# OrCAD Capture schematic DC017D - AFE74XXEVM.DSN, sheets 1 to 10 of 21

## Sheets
1 SHEET 21 - HARDWARE: size B; title: HARDWARE; rev: D; note: DC017 - AFE74XXEVM
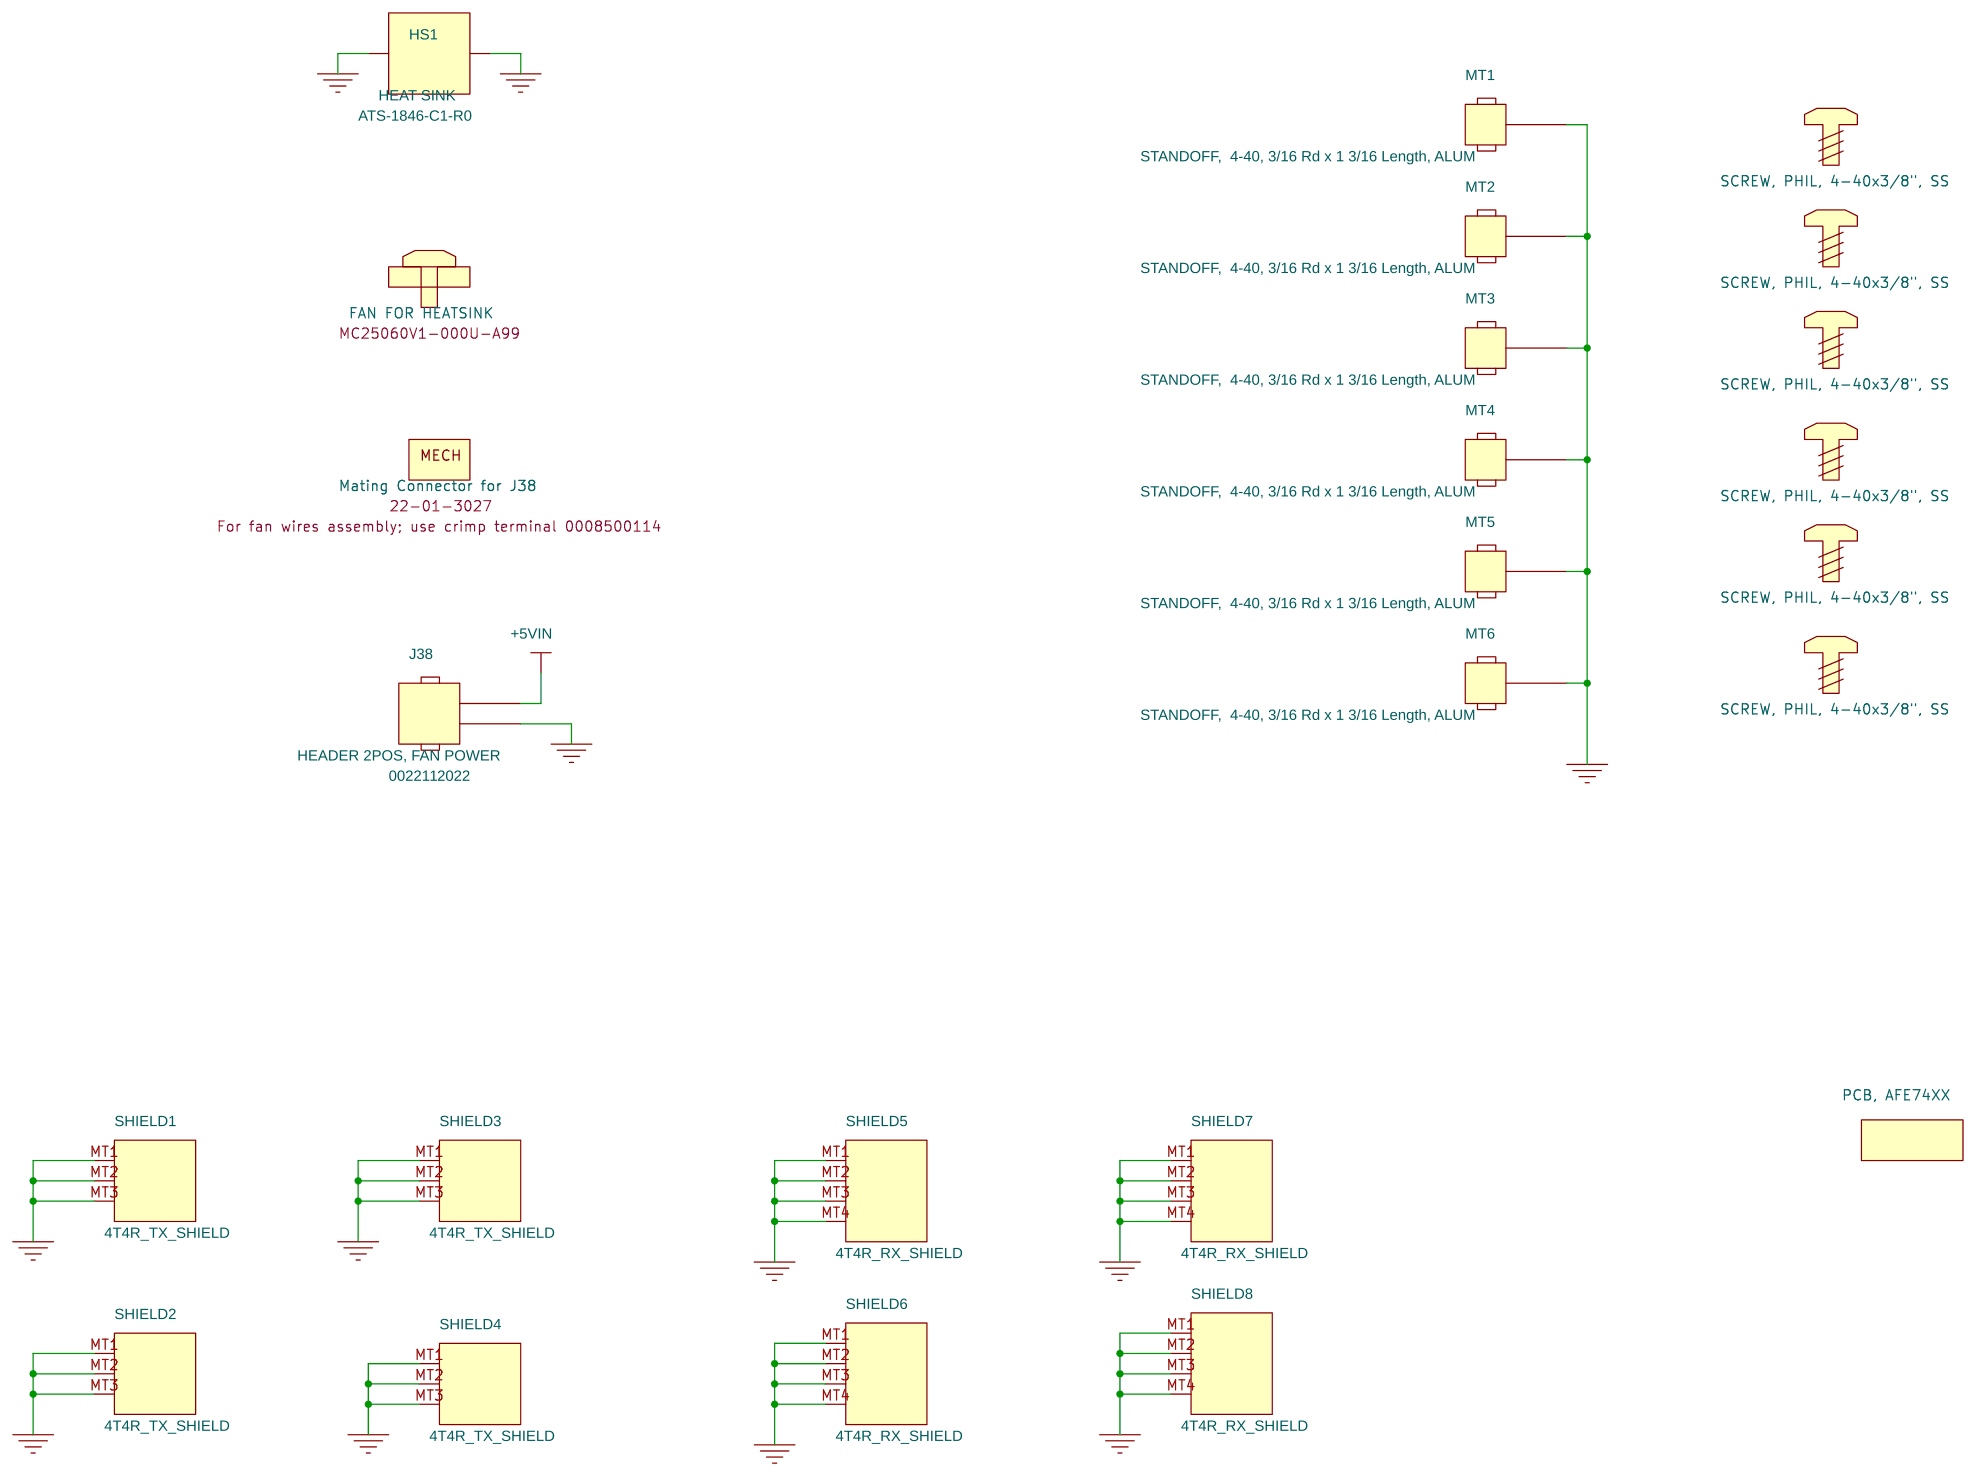
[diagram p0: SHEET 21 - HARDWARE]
2 SHEET 20 - POWER SUPPLIES: size B; title: POWER SUPPLIES +.9V, +1.8V
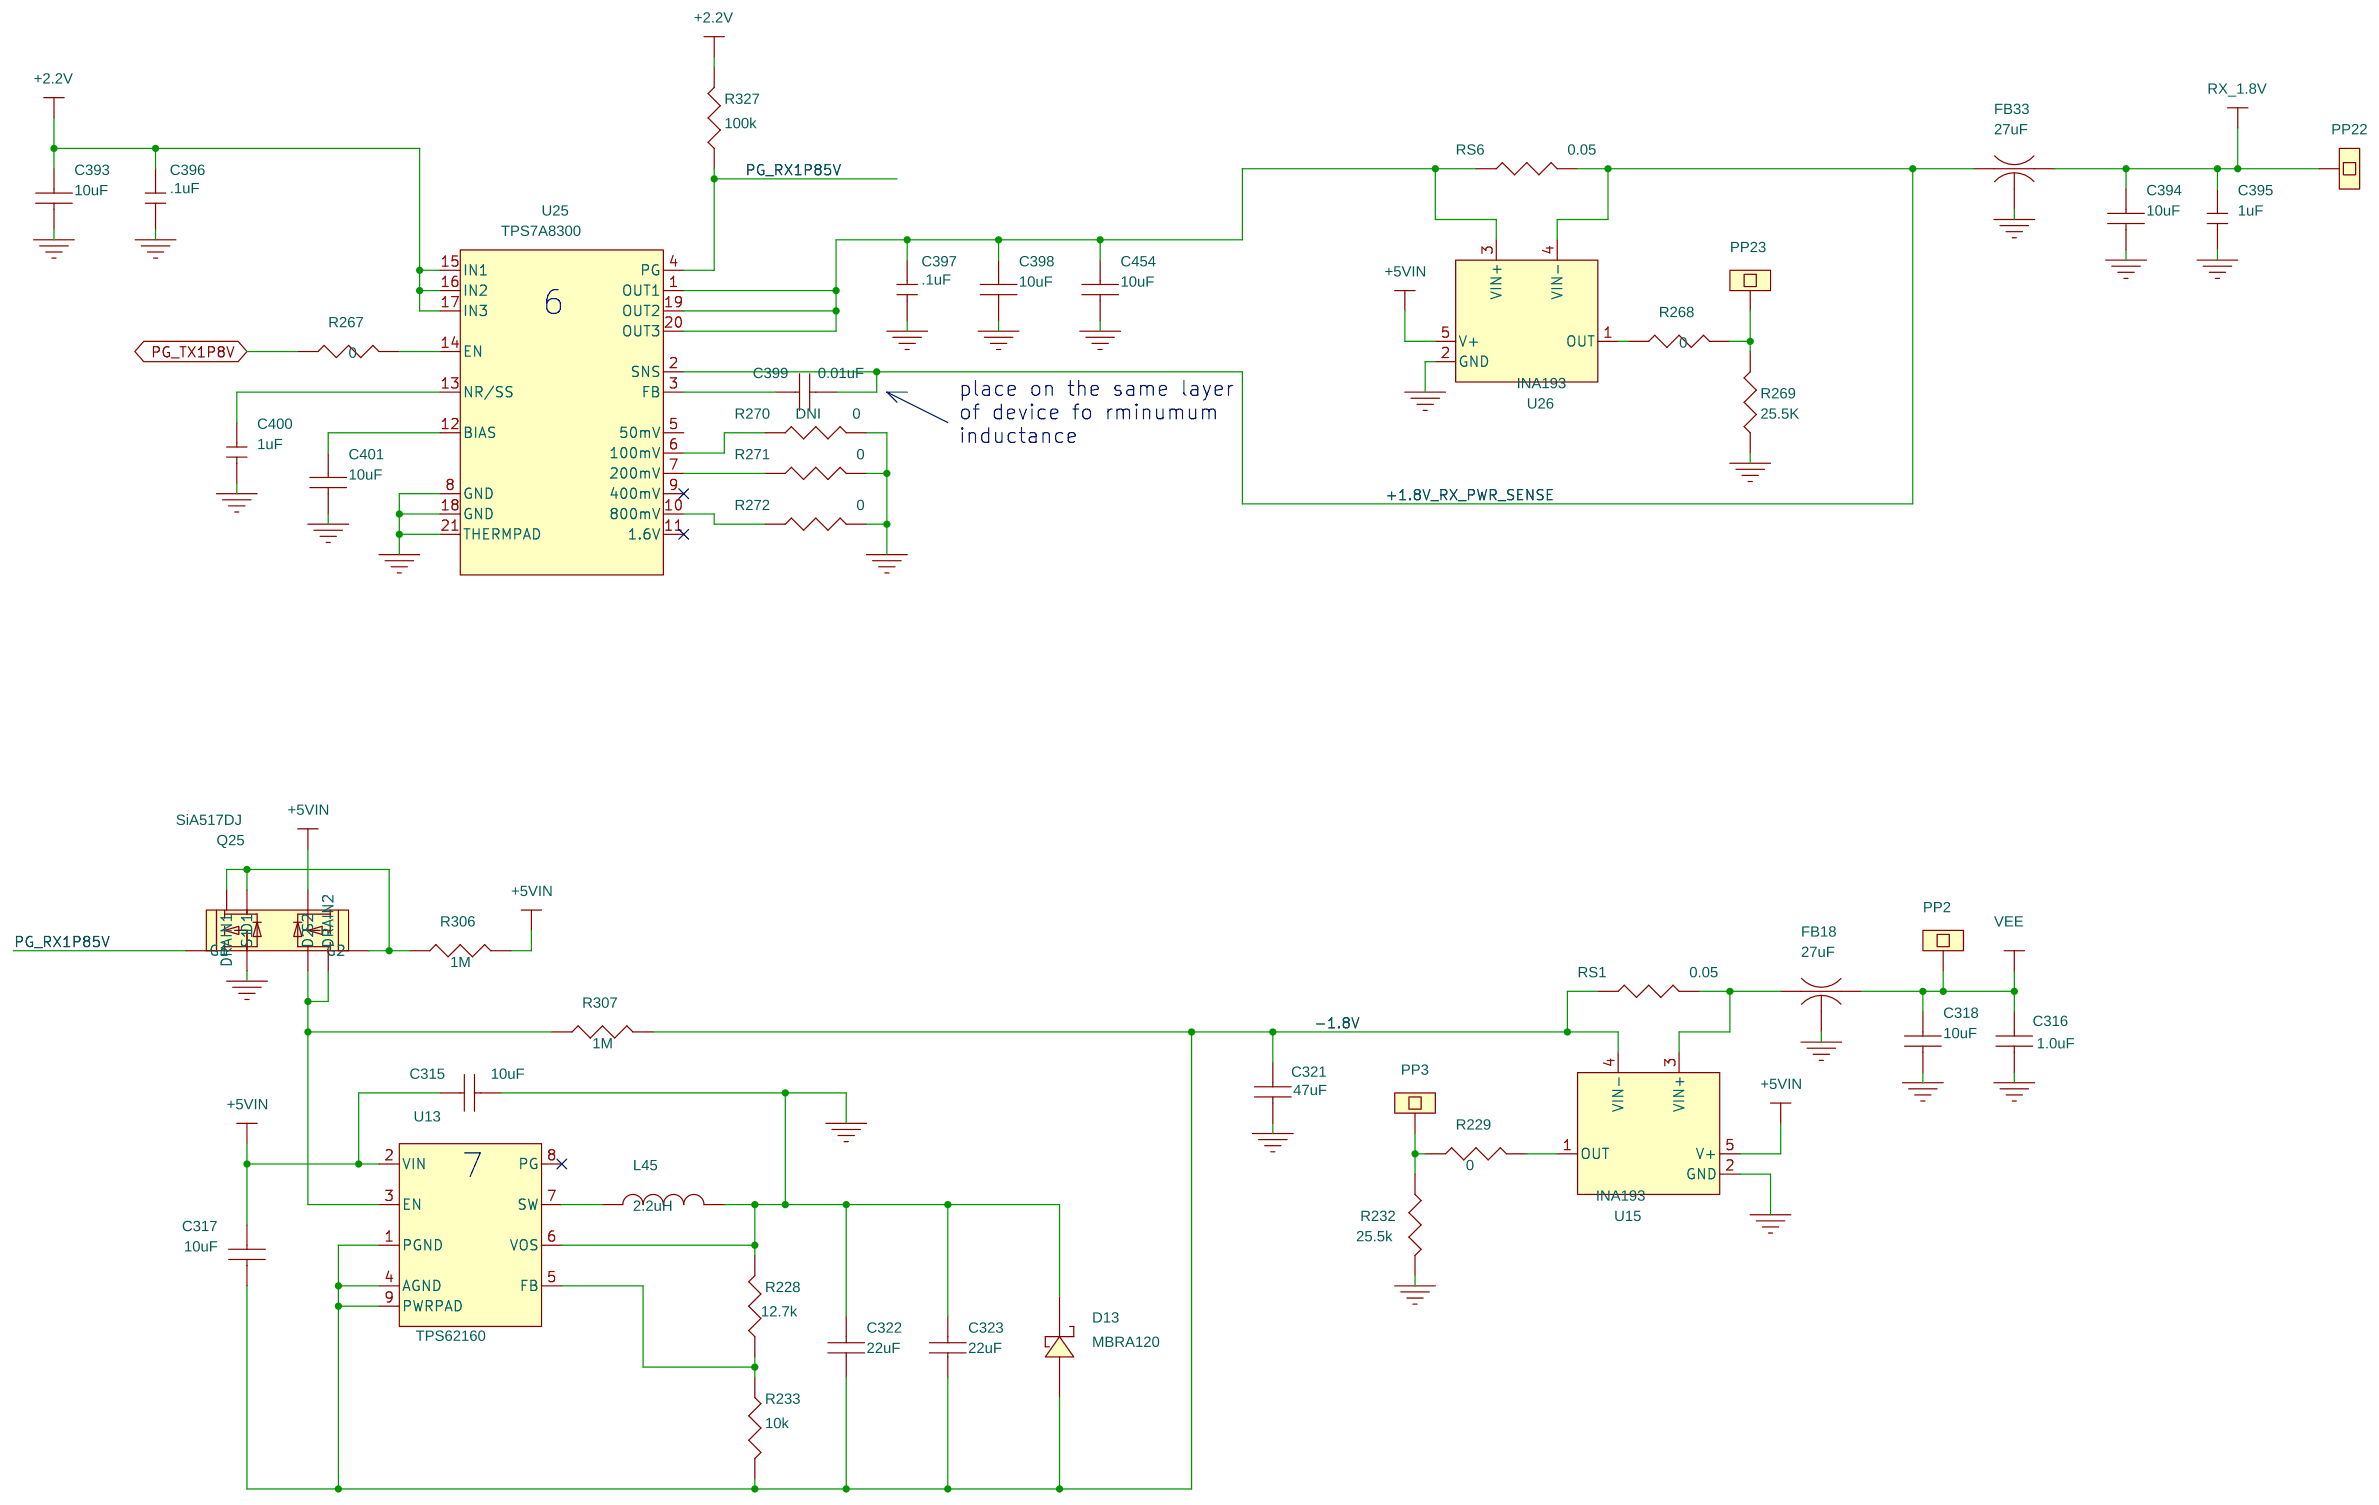
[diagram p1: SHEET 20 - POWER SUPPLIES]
3 SHEET 01 - COVER: title: COVER
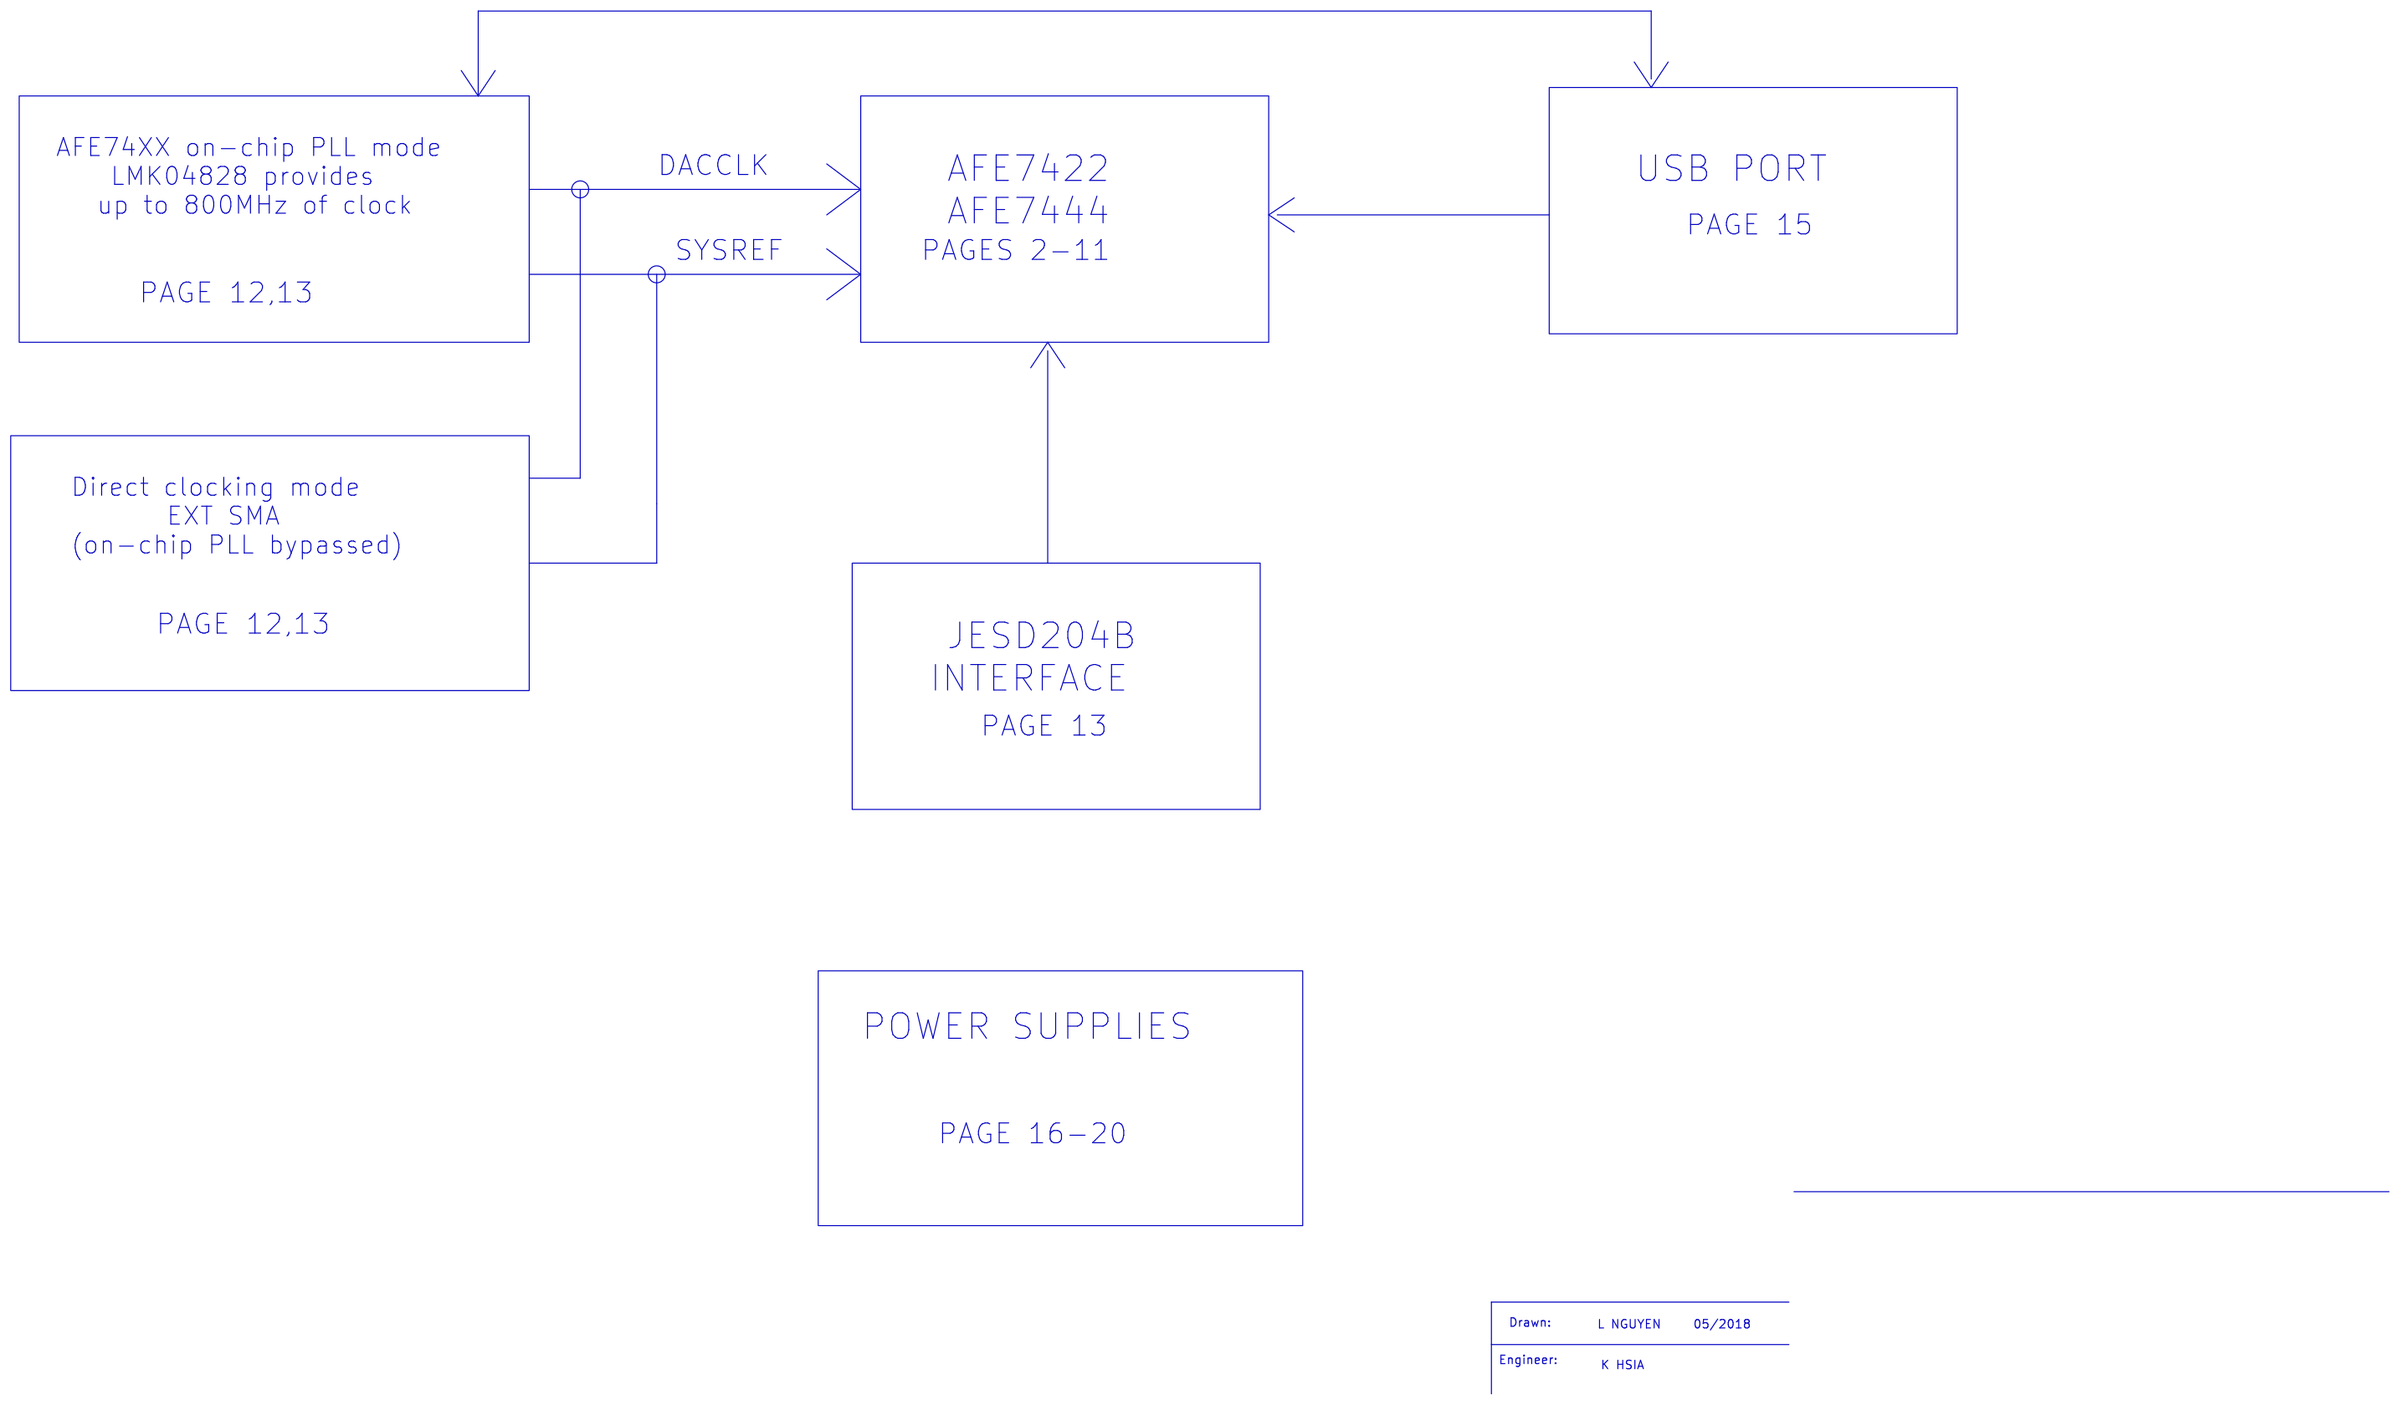
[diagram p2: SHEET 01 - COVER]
4 SHEET 02 - AFE RX & TX: size B; title: AFE CLKp/m, CLKOUTp/m, SYSREFp/m
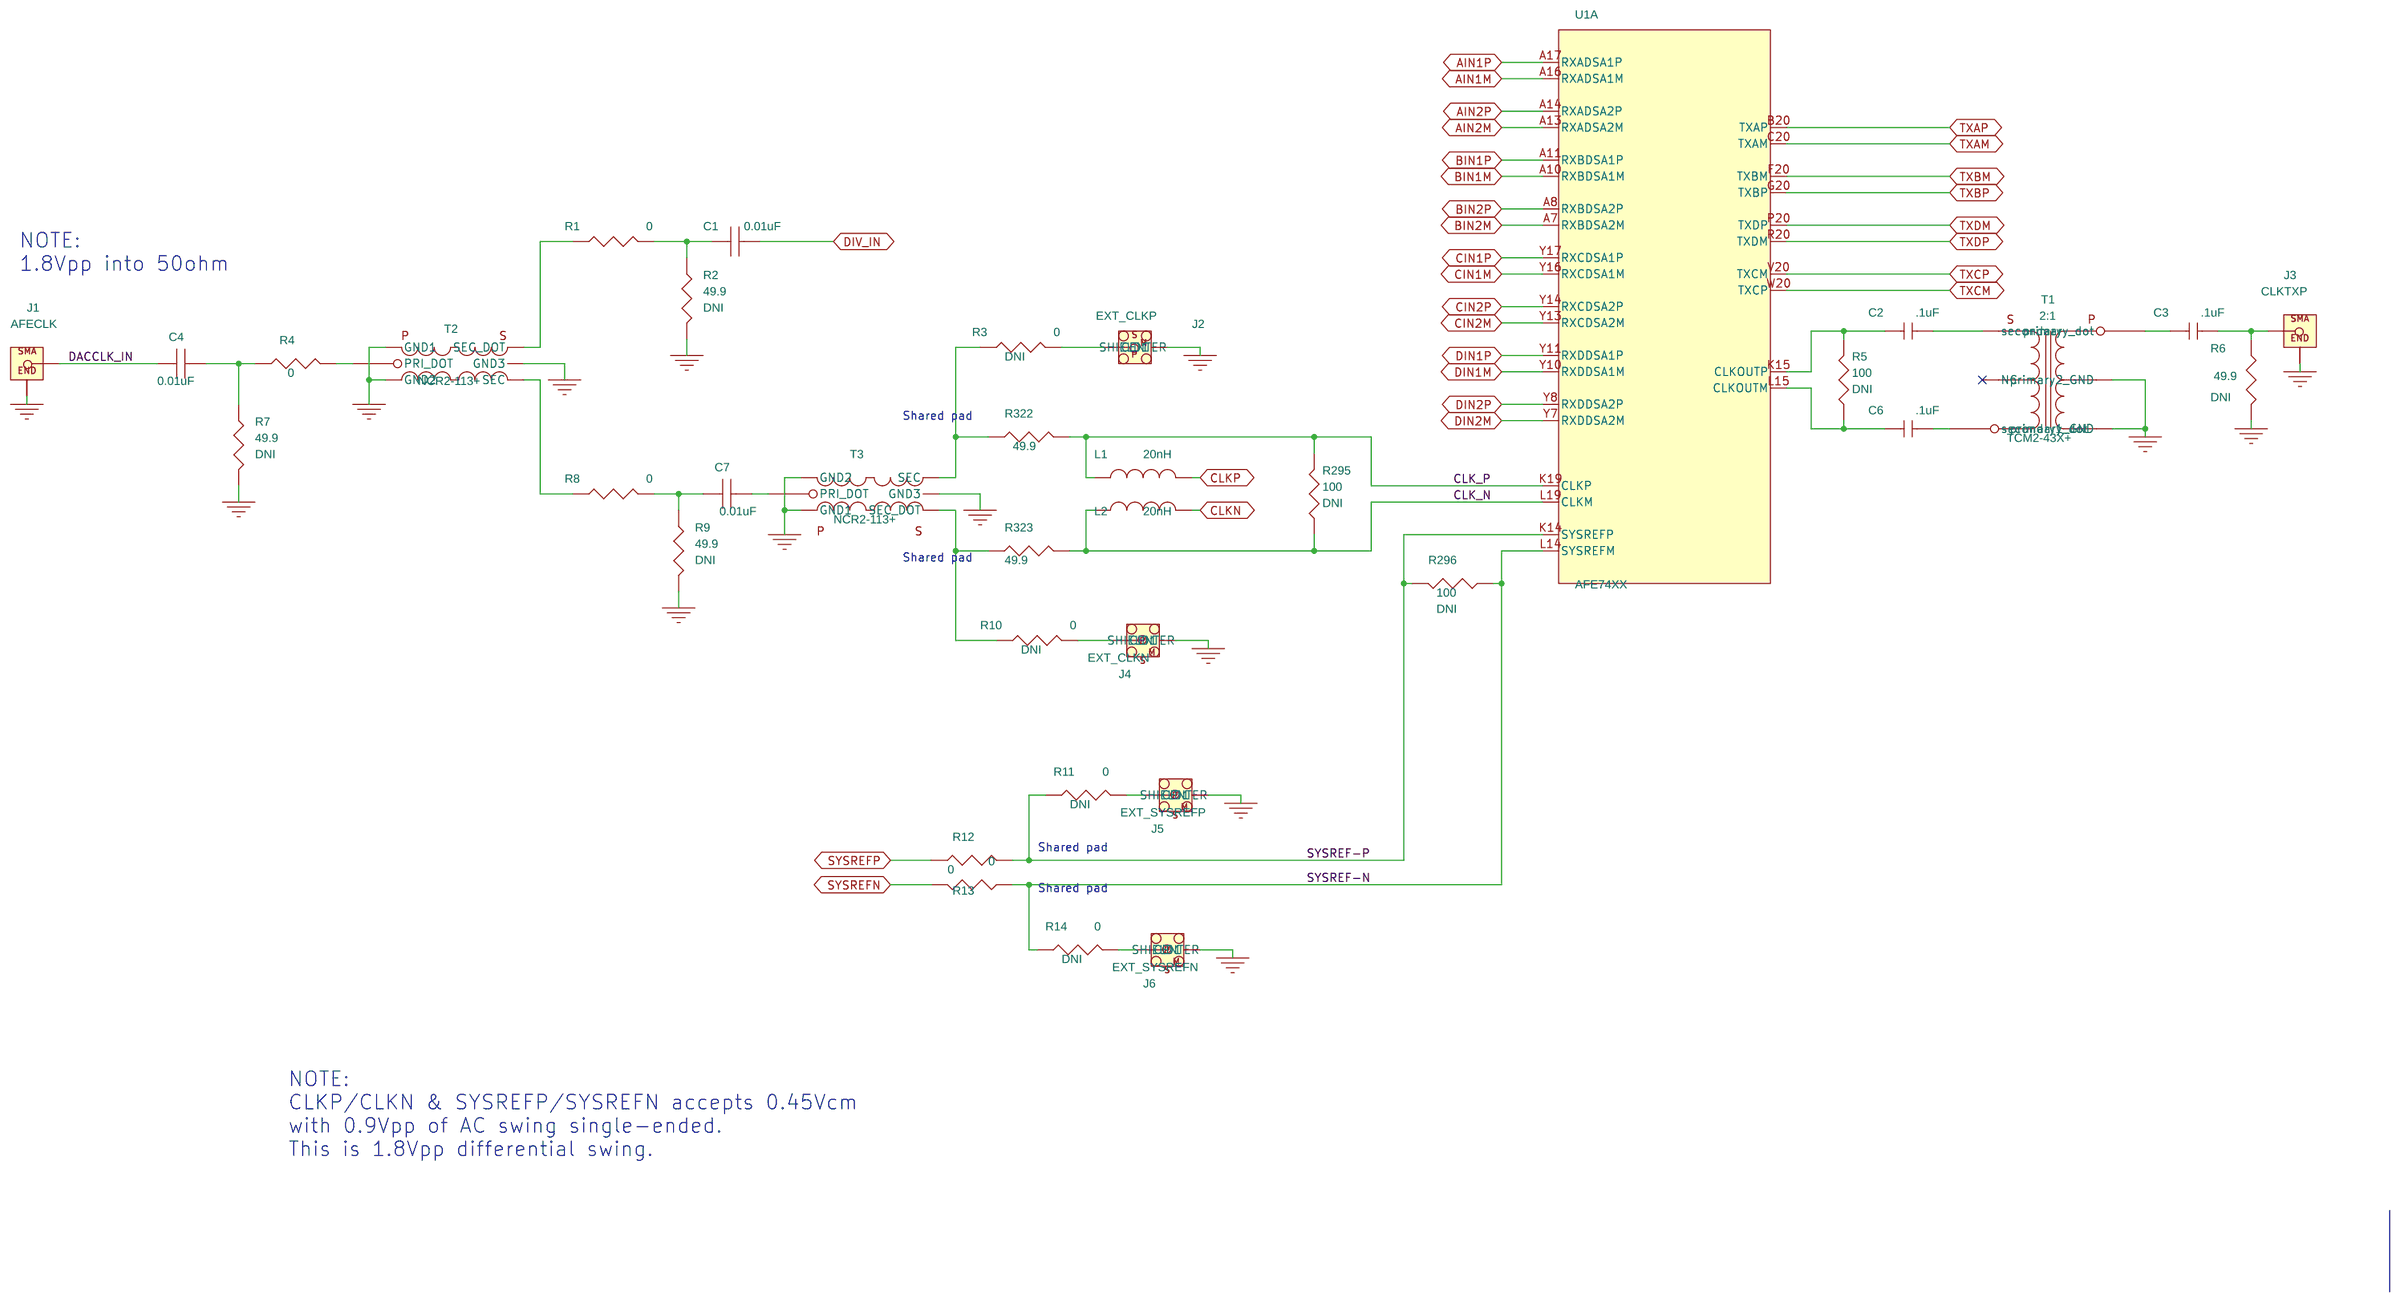
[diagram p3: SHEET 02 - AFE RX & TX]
5 SHEET 03 - AFE Serdes: size B; title: Serdes Lanes
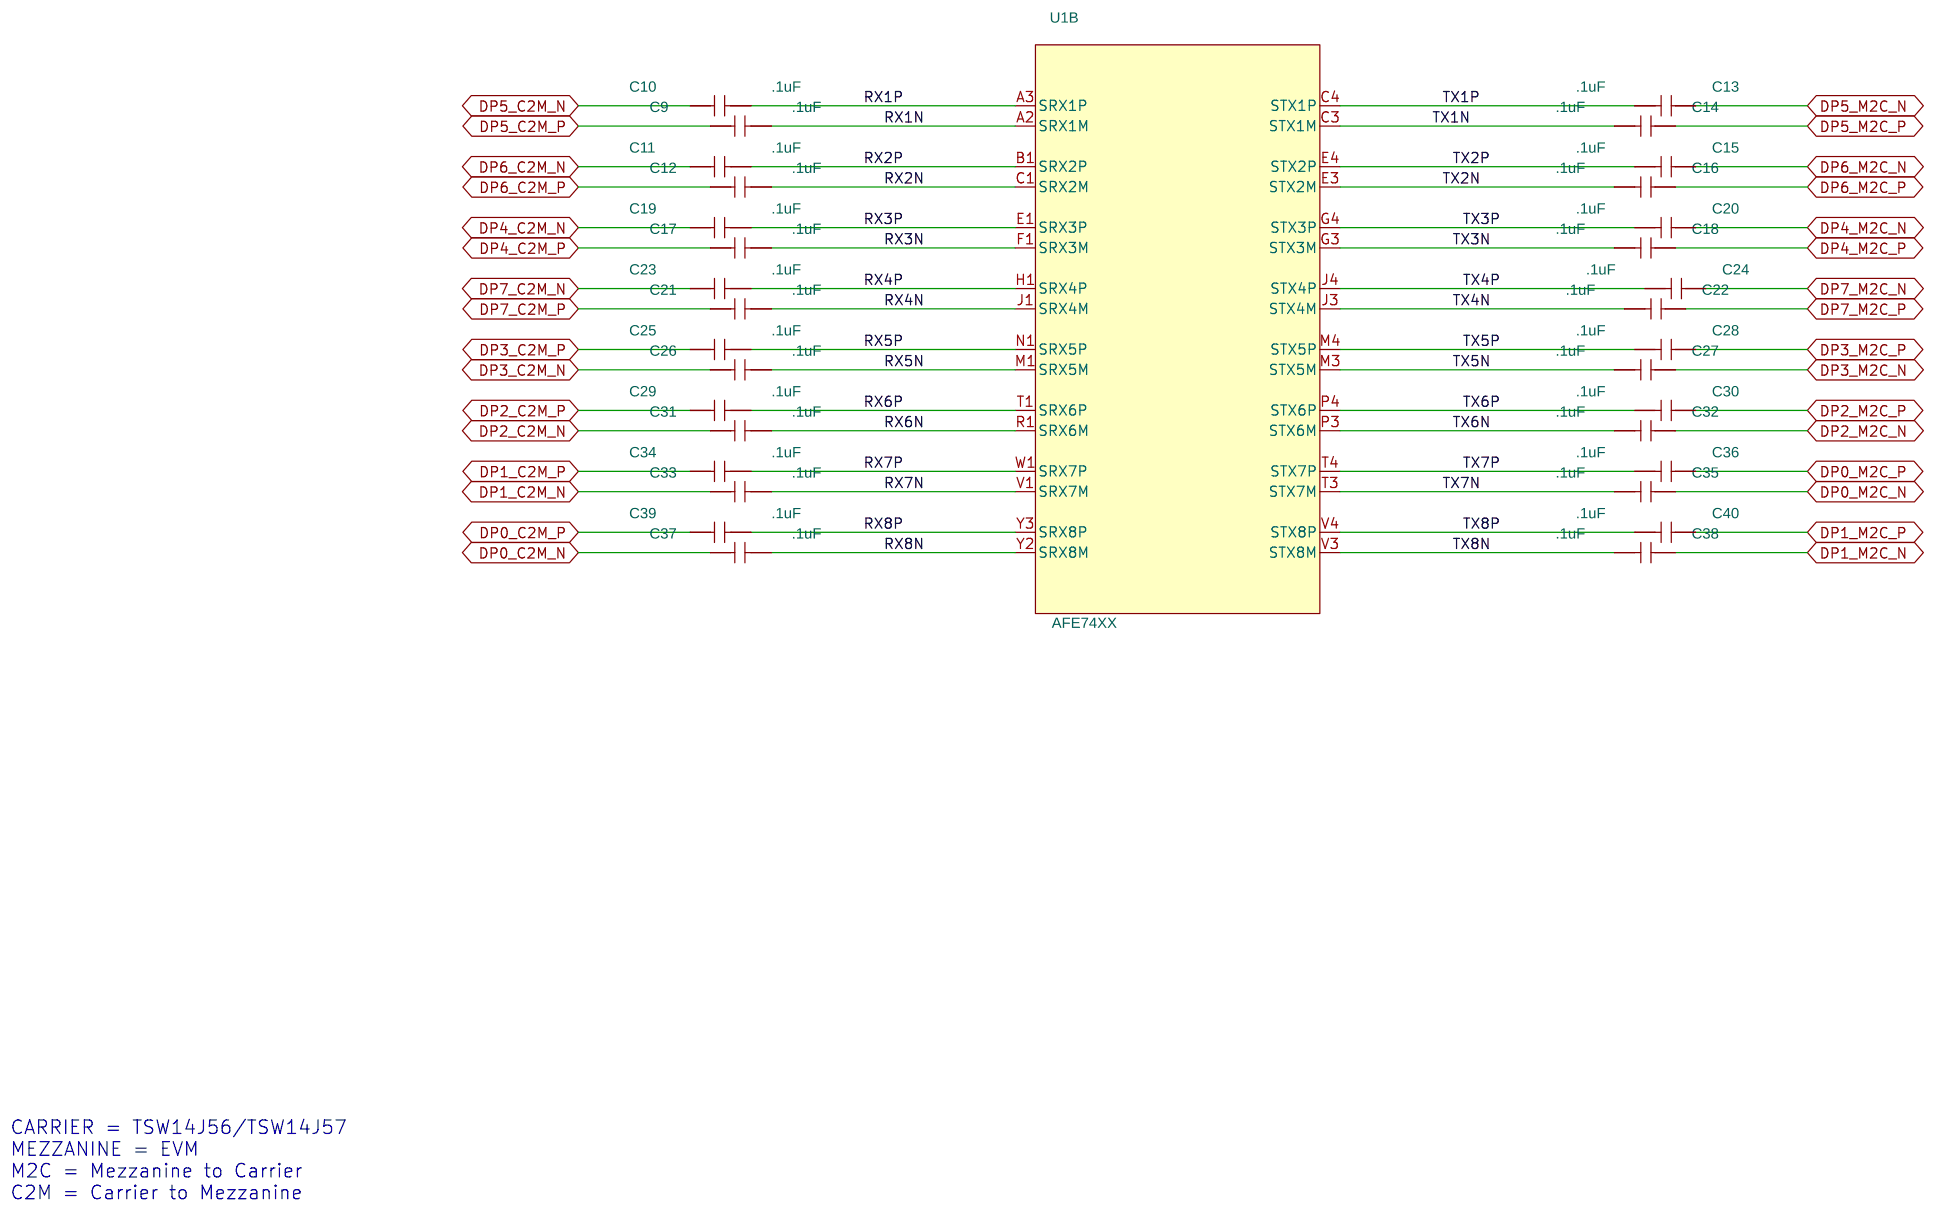
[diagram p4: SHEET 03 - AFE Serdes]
6 SHEET 04 - AFE: size B; title: DAC
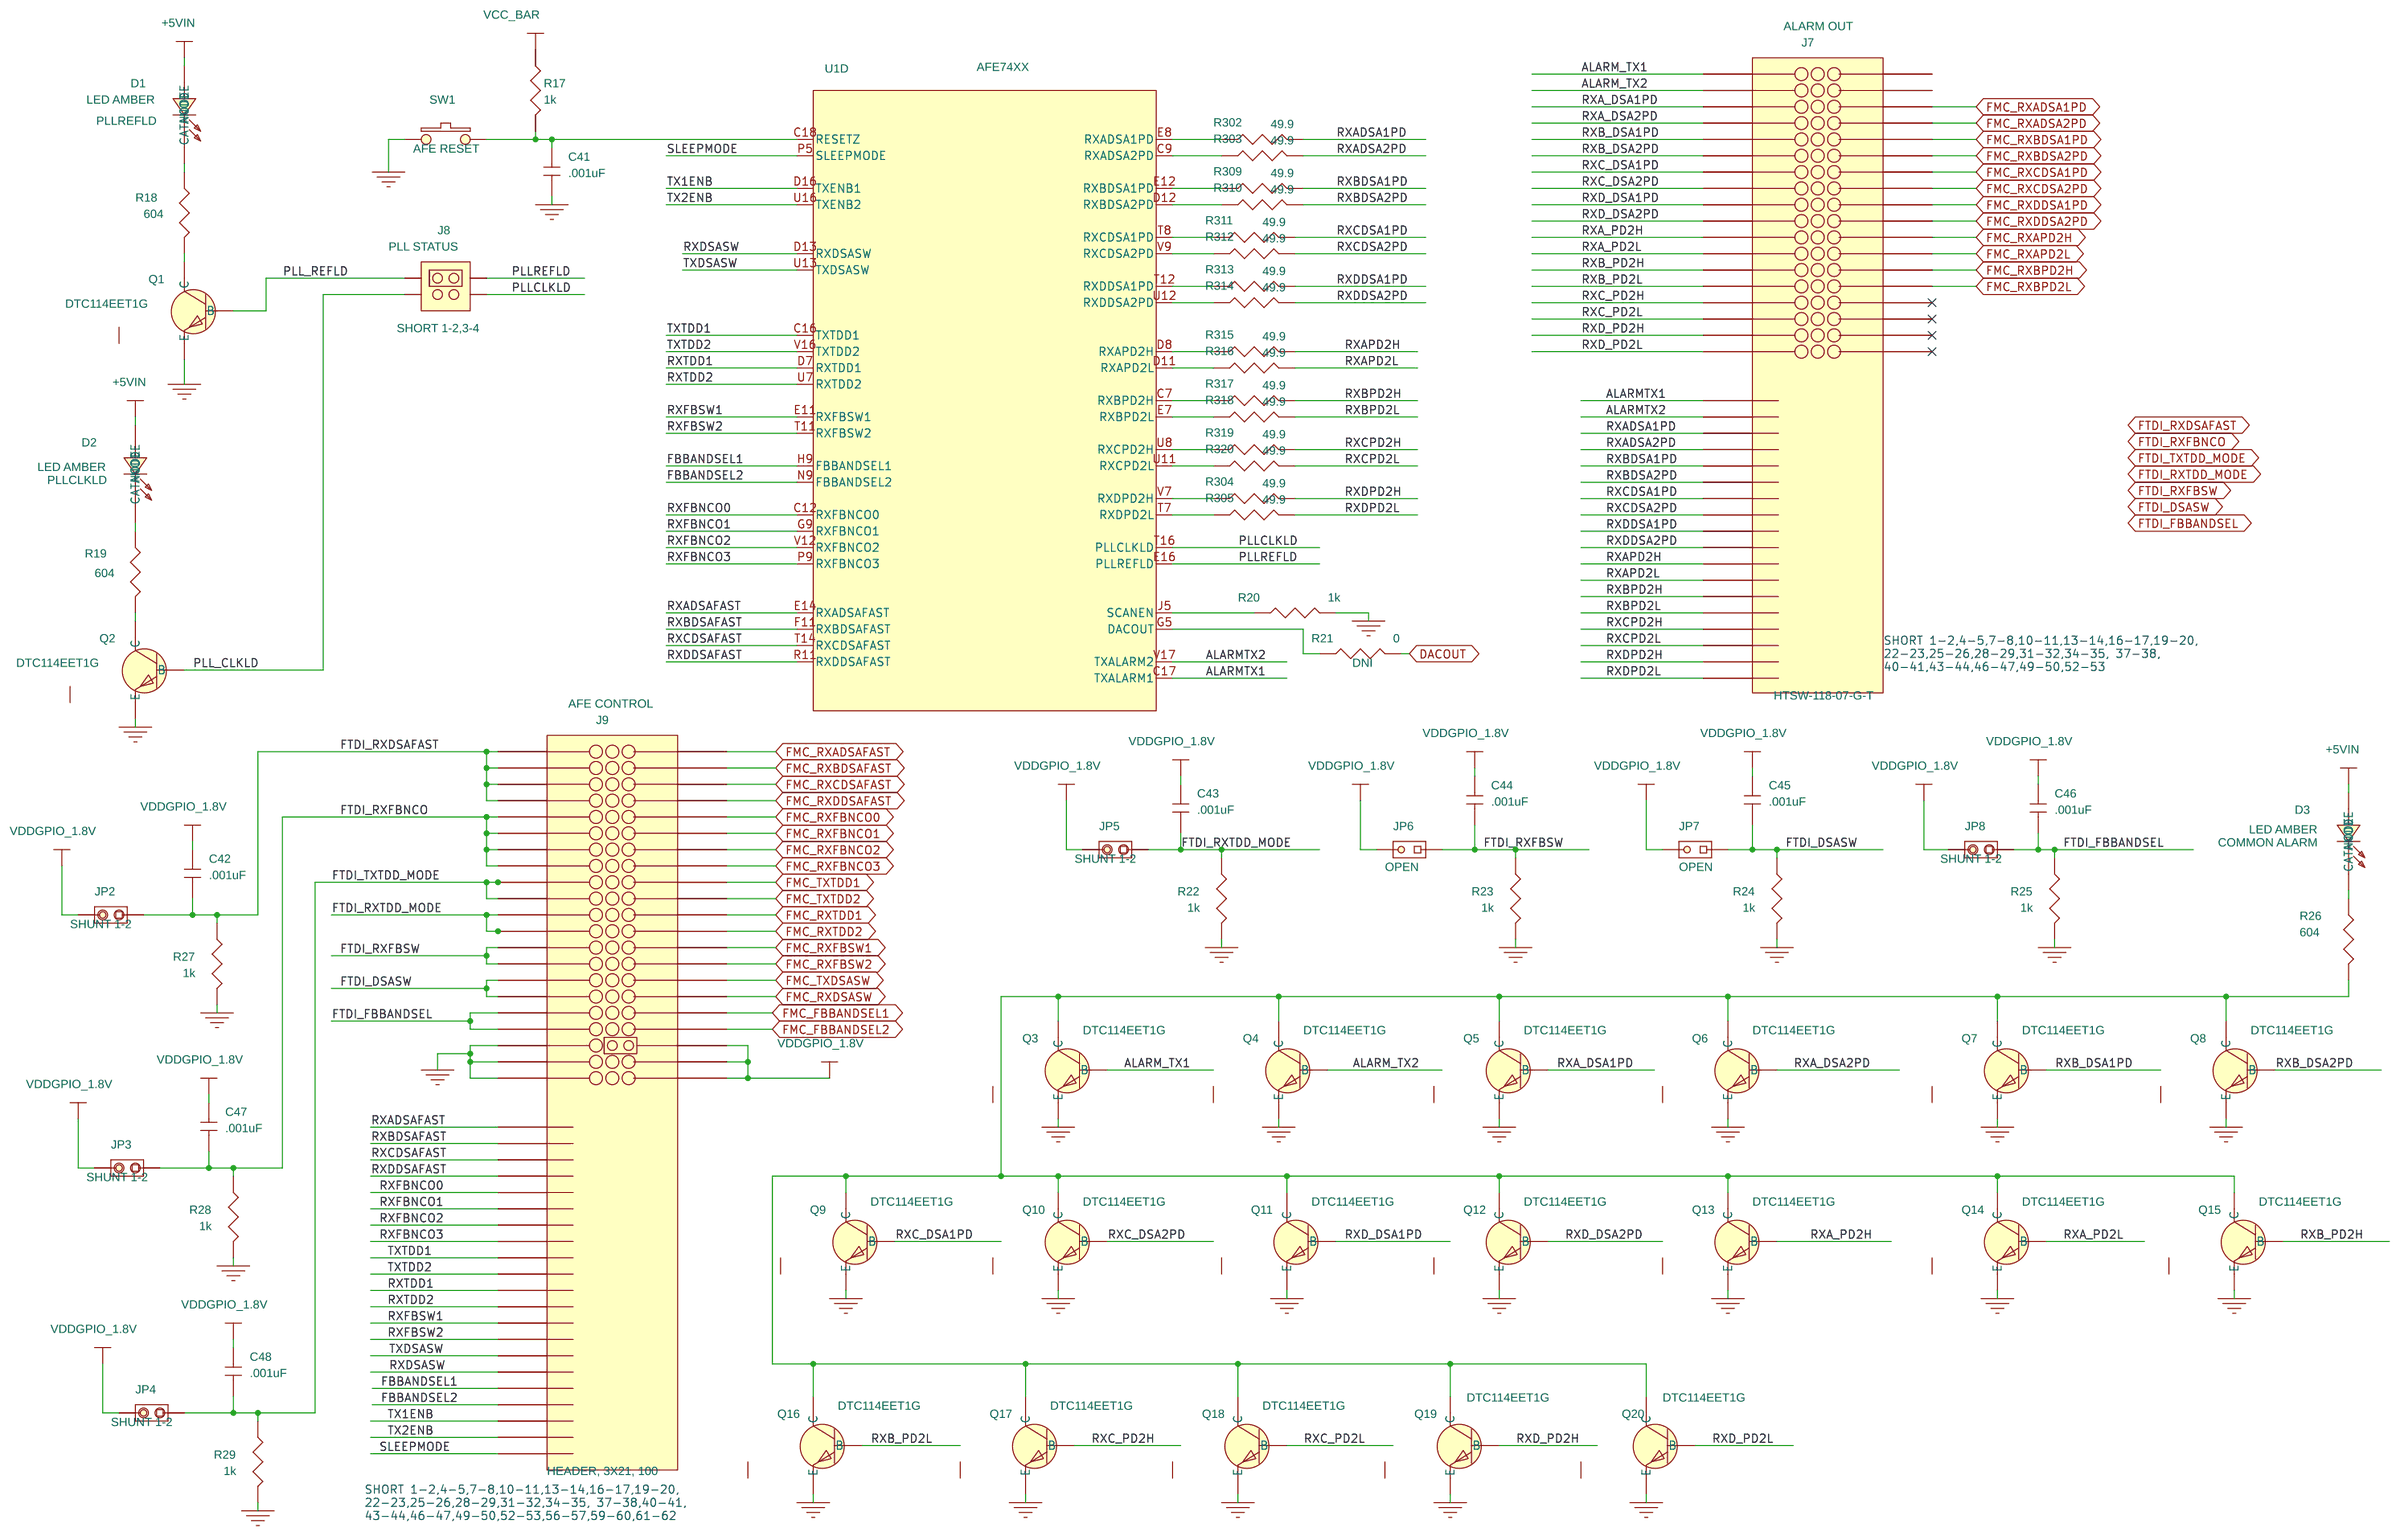
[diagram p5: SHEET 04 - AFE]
7 SHEET 05 - AFE: size B; title: DAC
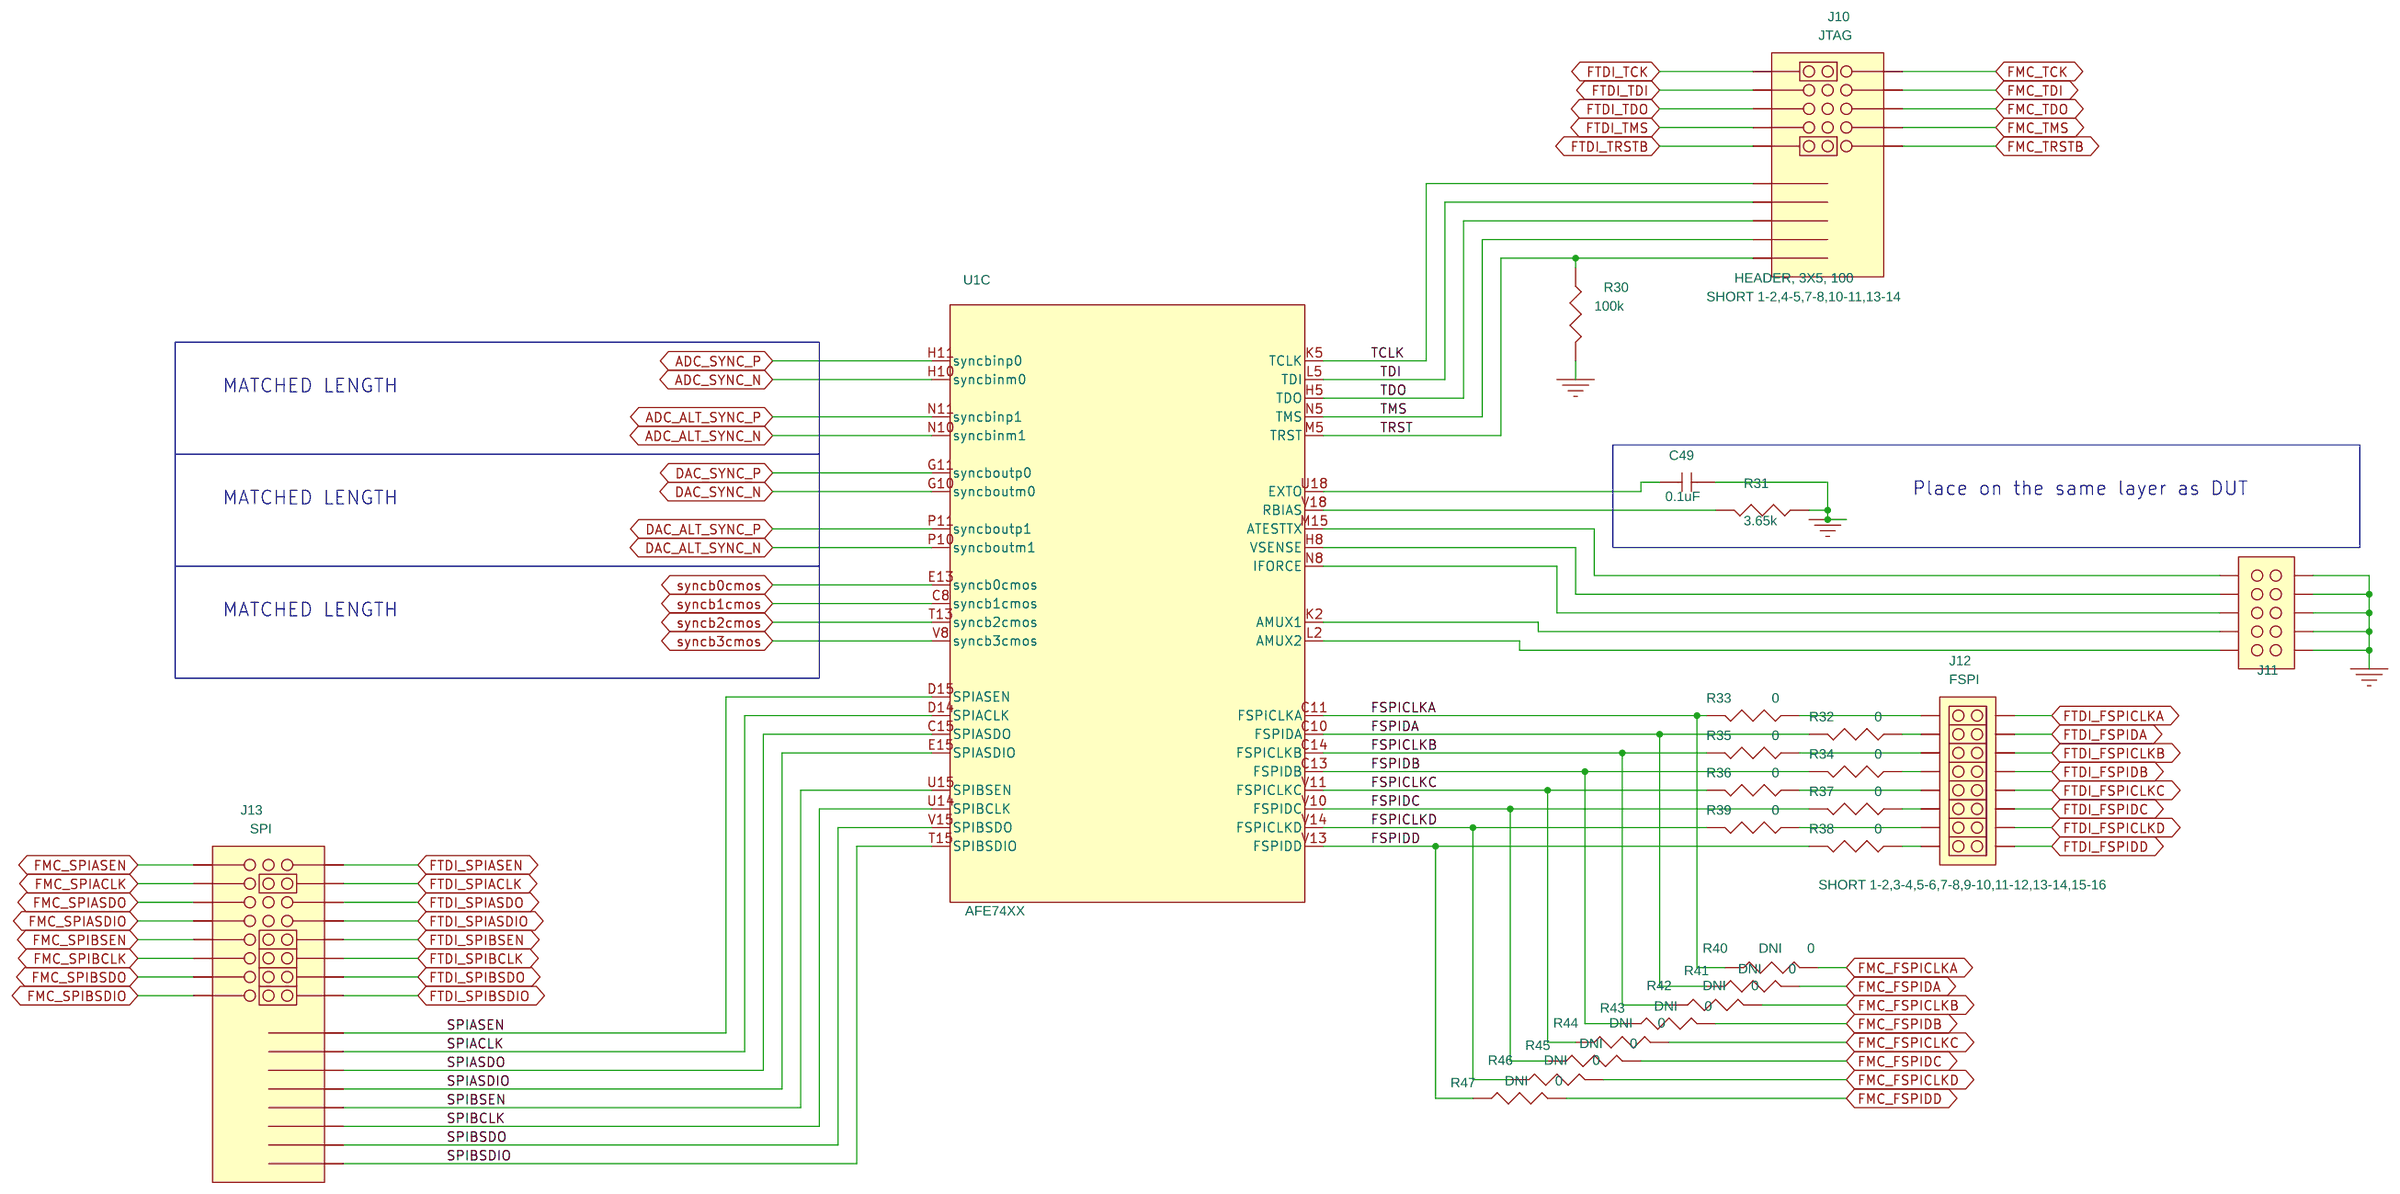
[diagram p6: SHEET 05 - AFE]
8 SHEET 06 - AFE POWER: size B; title: AFE POWER
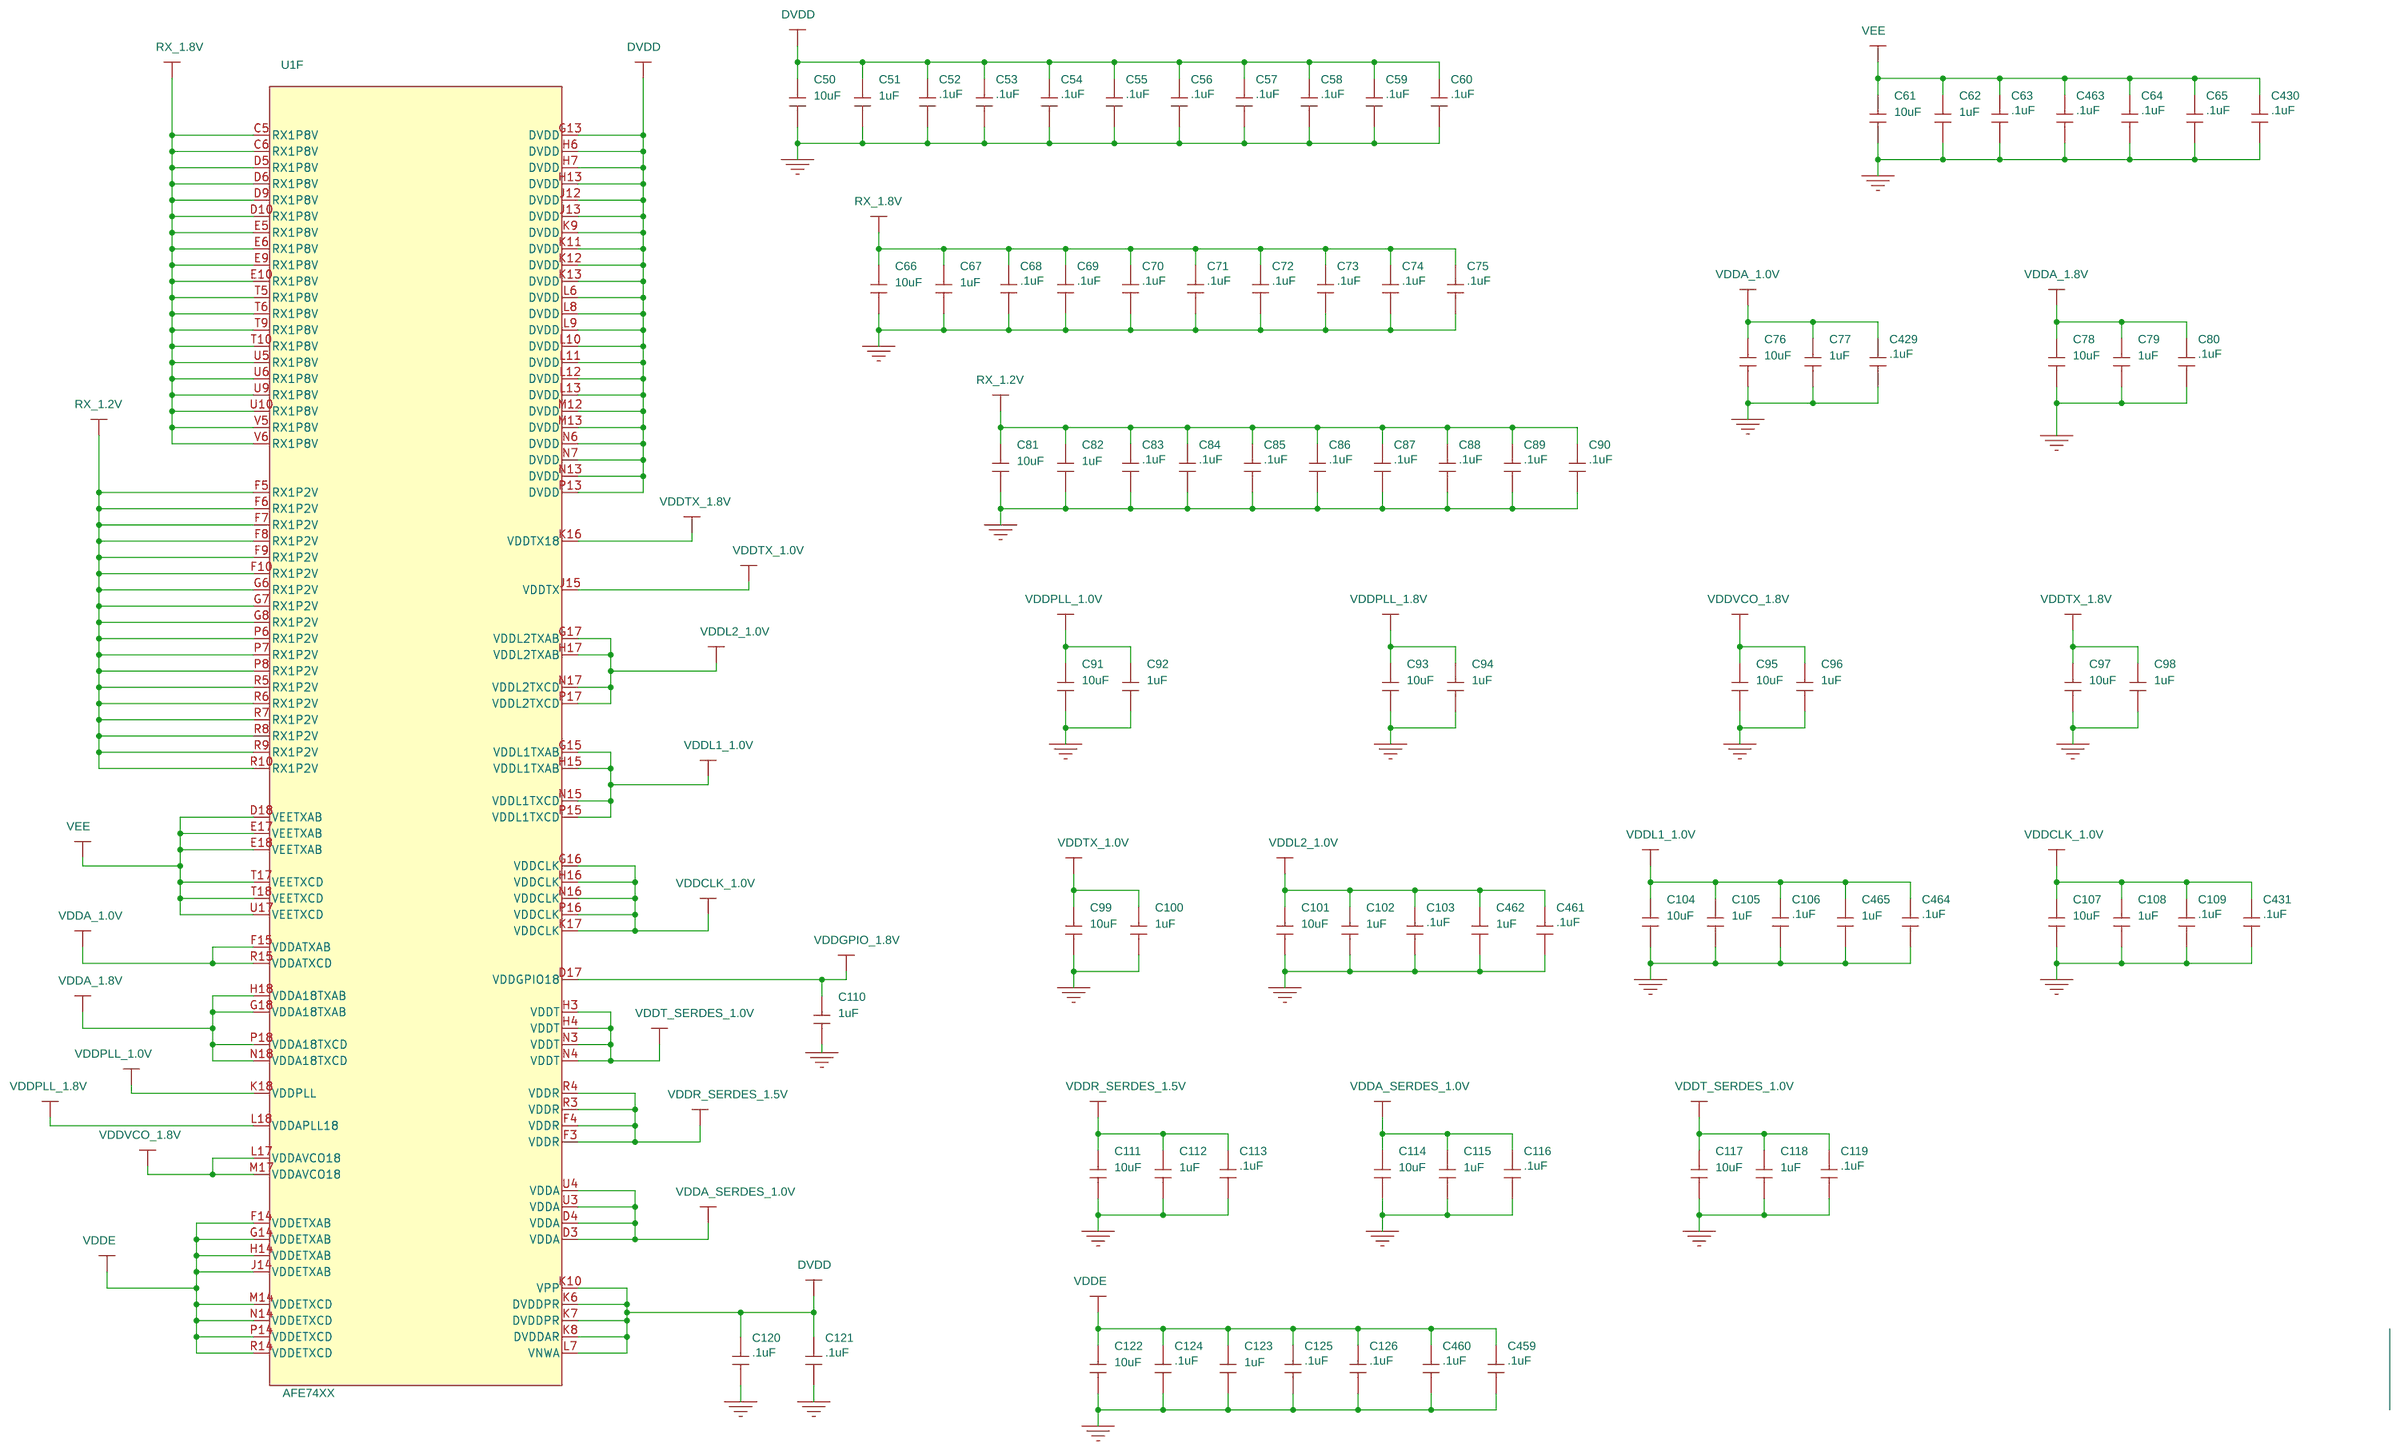
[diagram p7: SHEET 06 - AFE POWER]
9 SHEET 07 - AFE GROUND: size B; title: AFE POWER
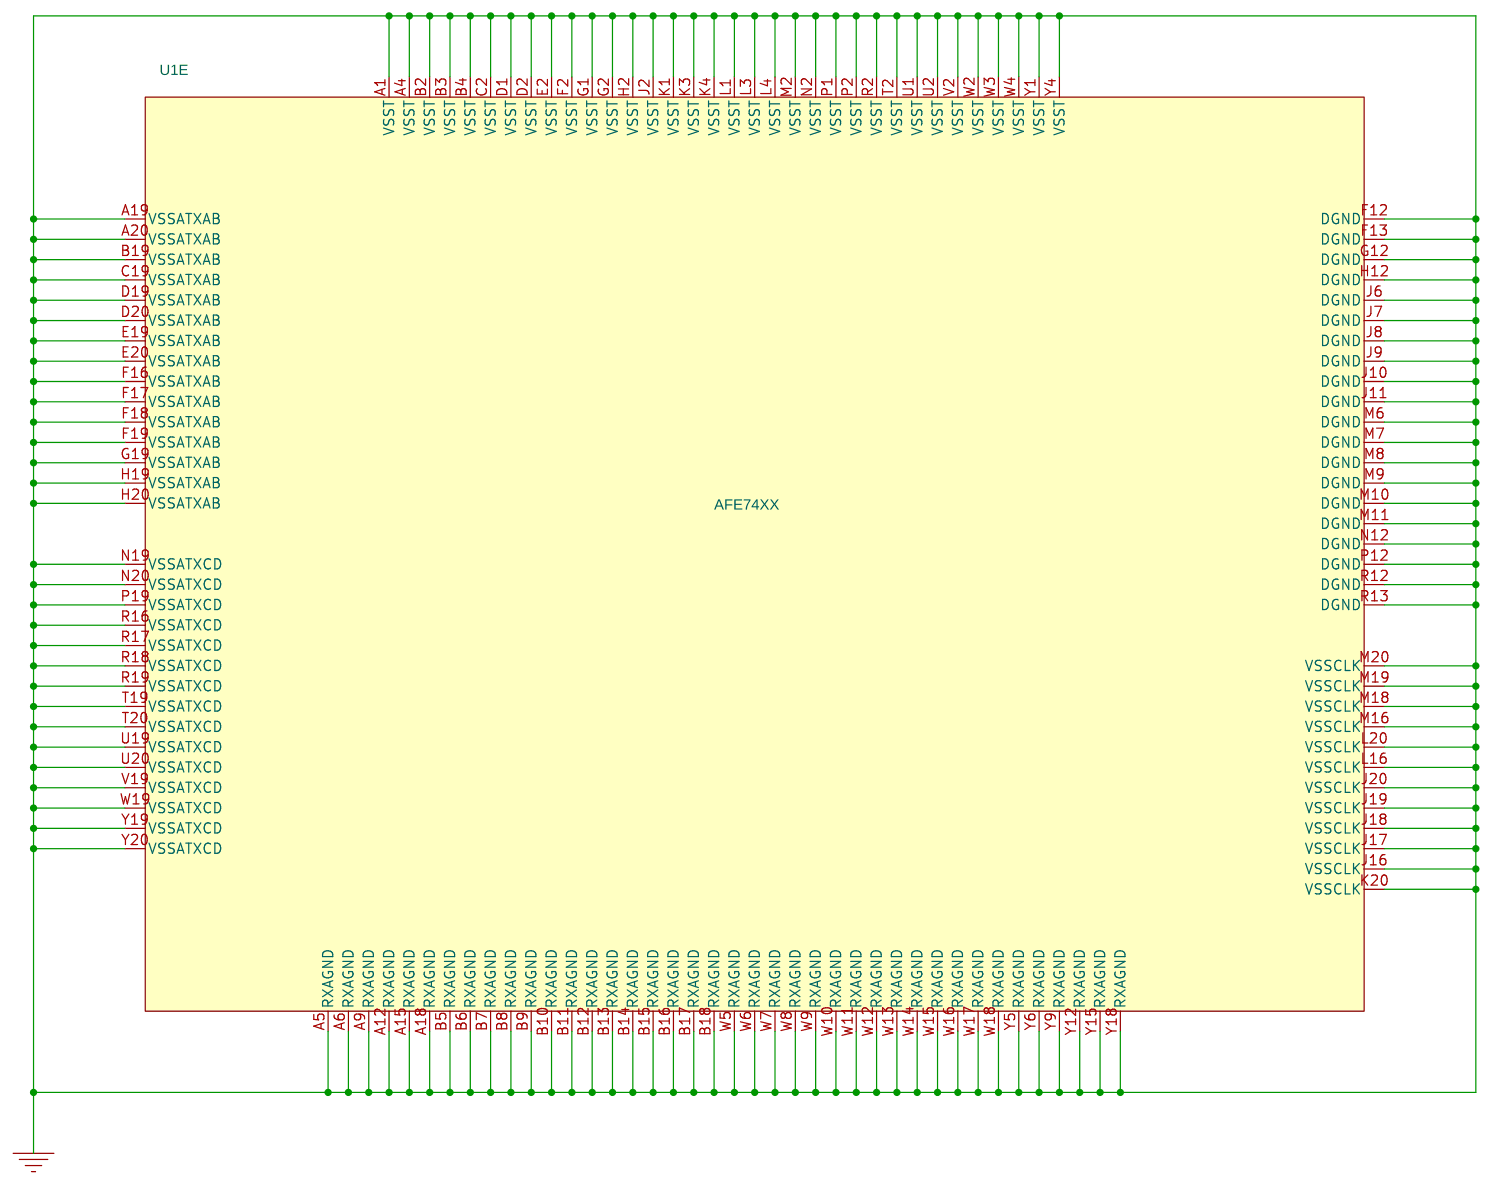
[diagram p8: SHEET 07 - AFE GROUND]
10 SHEET 08 - RX INPUTS: size B; title: AFE INPUTS
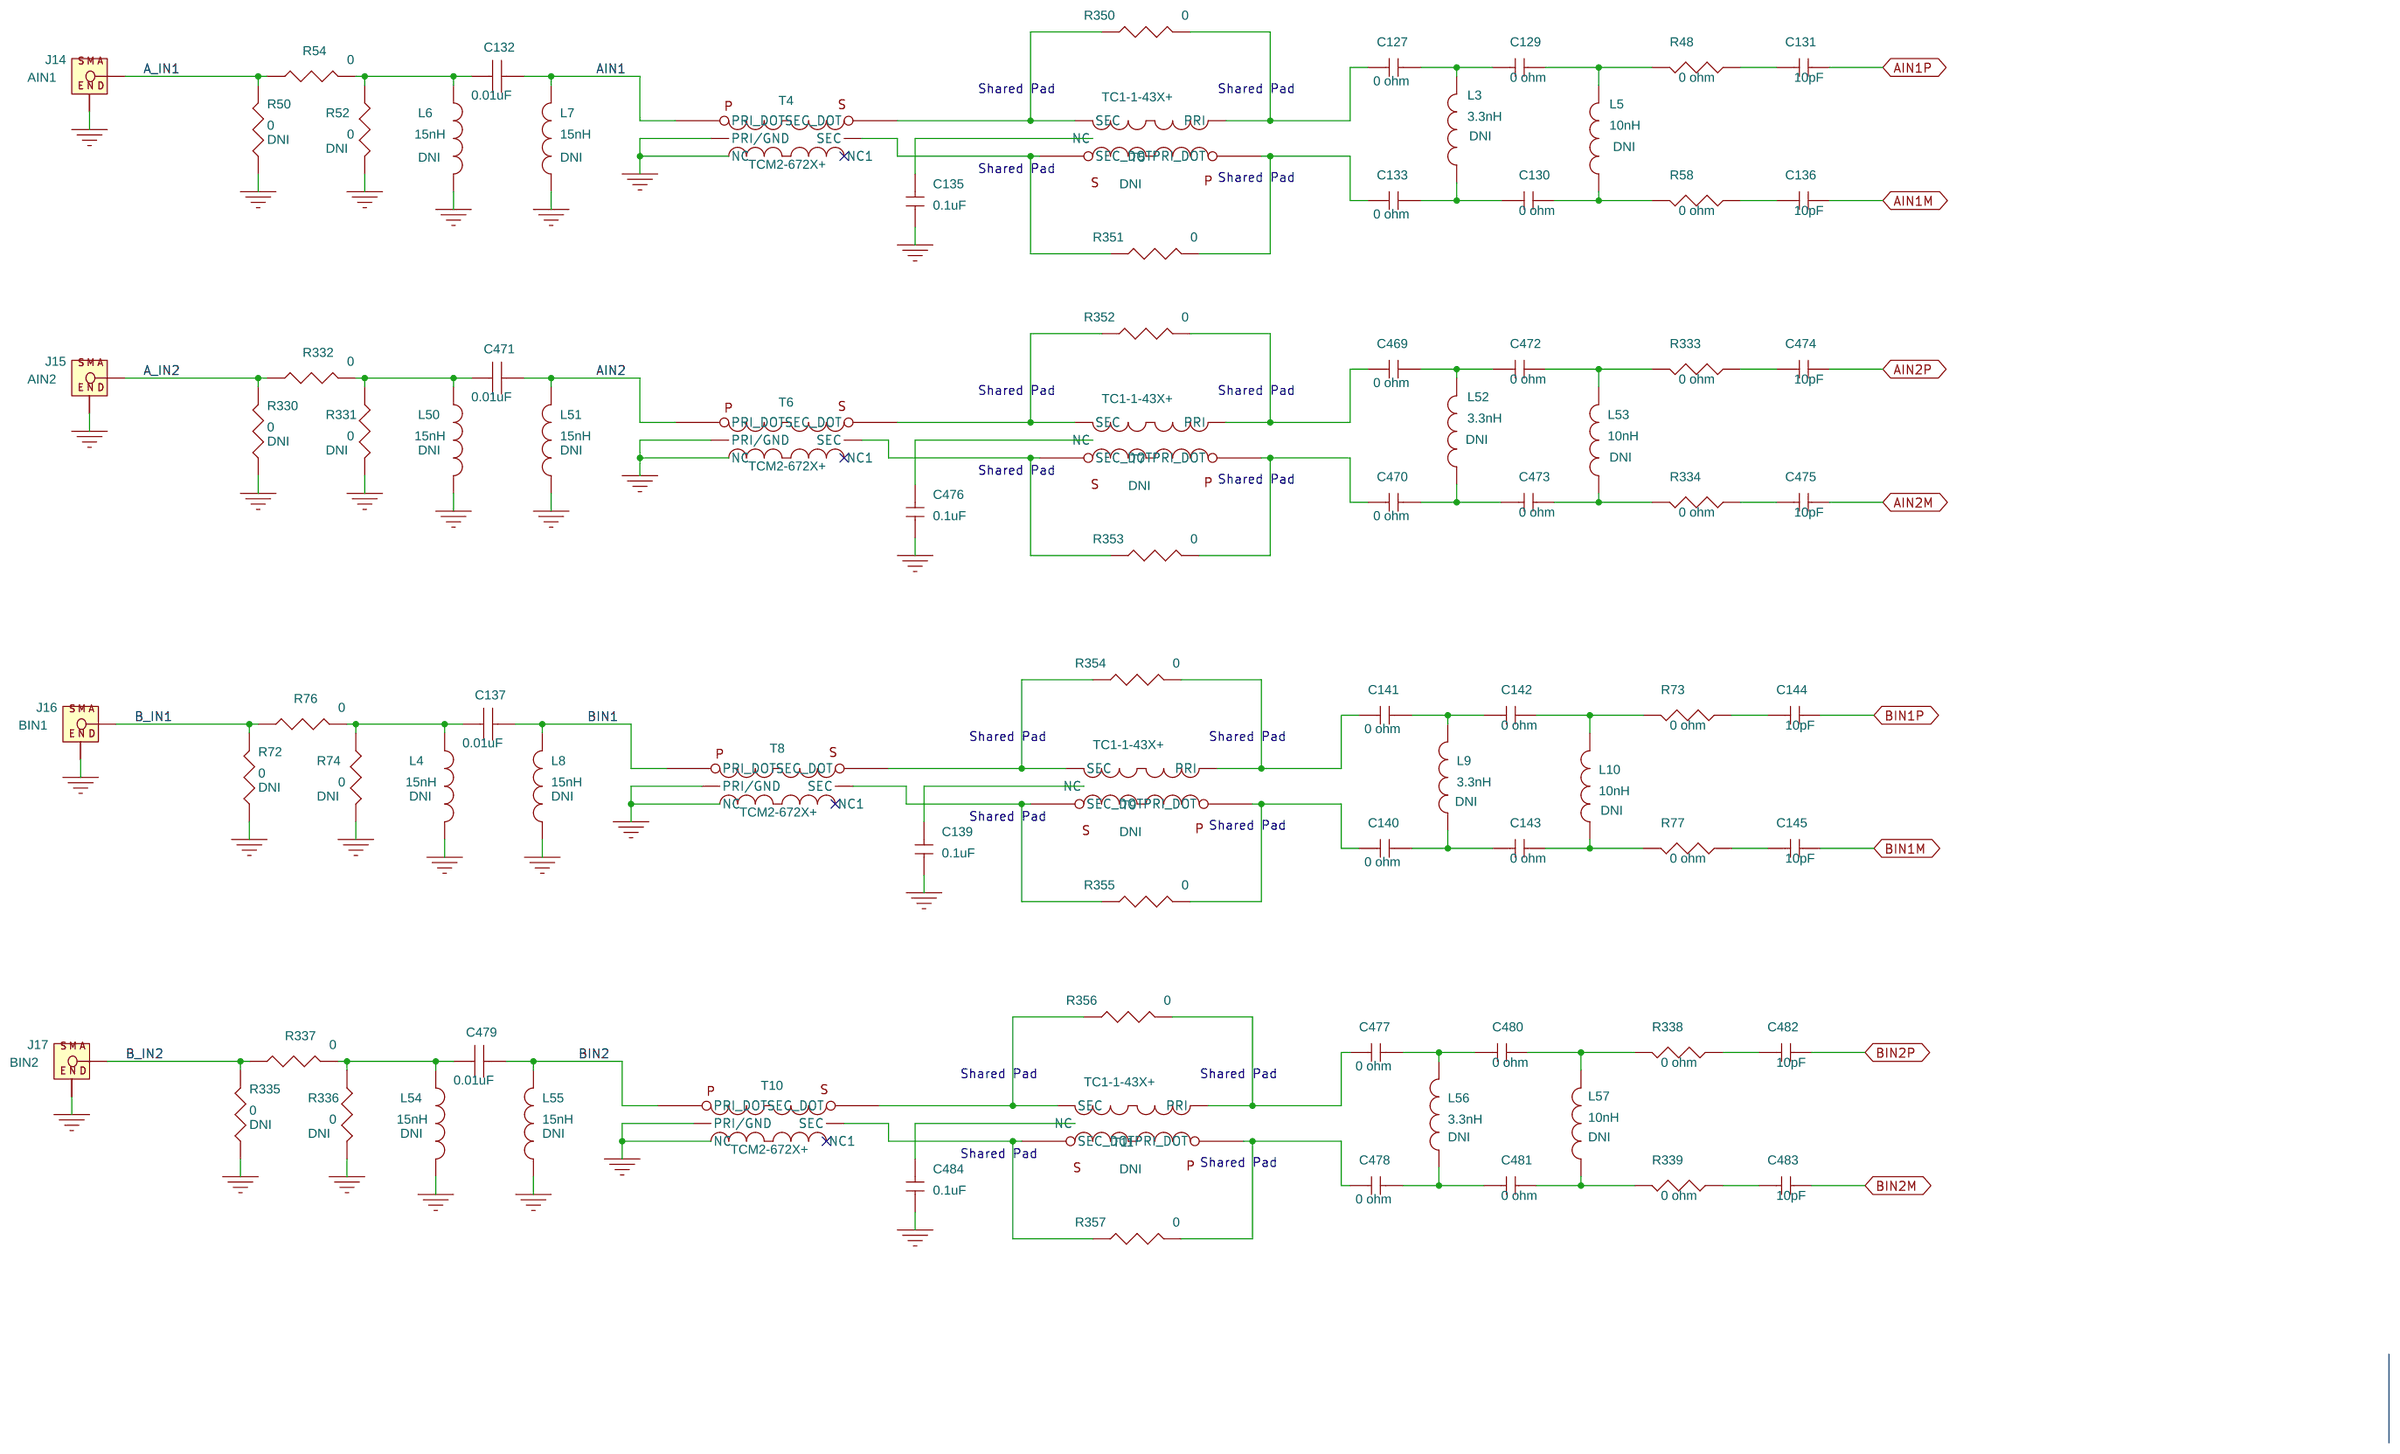
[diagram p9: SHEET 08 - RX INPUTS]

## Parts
sheet SHEET 02 - AFE RX & TX
C1  0.01uF  [0402]
C2  .1uF  [0201]
C3  .1uF  [0201]
C4  0.01uF  [0402]
C6  .1uF  [0201]
C7  0.01uF  [0402]
J1  SMA END LAUNCH  [SMA_SMEL_DUAL_PSF-S01_250x215]
J2  SMP CONN  [smp_b120]
J3  SMA END LAUNCH  [SMA_SMEL_DUAL_PSF-S01_250x215]
J4  SMP CONN  [smp_b120]
J5  SMP CONN  [smp_b120]
J6  SMP CONN  [smp_b120]
L1  20nH  [0402]
L2  20nH  [0402]
R1  0  [0402]
R2  49.9  [0402]
R3  0  [0402]
R4  0  [0402]
R5  100  [0201]
R6  49.9  [0201]
R7  49.9  [0402]
R8  0  [0402]
R9  49.9  [0402]
R10  0  [0402]
R11  0  [0402]
R12  0  [0201]
R13  0  [0201]
R14  0  [0402]
R295  100  [0201]
R296  100  [0201]
R322  49.9  [0201]
R323  49.9  [0201]
T1  TCM2-43X+  [TFMR_6_160x150_50]
T2  NCR2-113+  [BALUN_6_NCR2]
T3  NCR2-113+  [BALUN_6_NCR2]
sheet SHEET 03 - AFE Serdes
C9  .1uF  [0201]
C10  .1uF  [0201]
C11  .1uF  [0201]
C12  .1uF  [0201]
C13  .1uF  [0201]
C14  .1uF  [0201]
C15  .1uF  [0201]
C16  .1uF  [0201]
C17  .1uF  [0201]
C18  .1uF  [0201]
C19  .1uF  [0201]
C20  .1uF  [0201]
C21  .1uF  [0201]
C22  .1uF  [0201]
C23  .1uF  [0201]
C24  .1uF  [0201]
C25  .1uF  [0201]
C26  .1uF  [0201]
C27  .1uF  [0201]
C28  .1uF  [0201]
C29  .1uF  [0201]
C30  .1uF  [0201]
C31  .1uF  [0201]
C32  .1uF  [0201]
C33  .1uF  [0201]
C34  .1uF  [0201]
C35  .1uF  [0201]
C36  .1uF  [0201]
C37  .1uF  [0201]
C38  .1uF  [0201]
C39  .1uF  [0201]
C40  .1uF  [0201]
sheet SHEET 04 - AFE
C41  .001uF  [0402]
C42  .001uF  [0402]
C43  .001uF  [0402]
C44  .001uF  [0402]
C45  .001uF  [0402]
C46  .001uF  [0402]
C47  .001uF  [0402]
C48  .001uF  [0402]
D1  LED AMBER  [LED_0603]
D2  LED AMBER  [LED_0603]
D3  LED AMBER  [LED_0603]
J7  HTSW-118-07-G-T  [HDR_THVT_3x18_100_M]
J8  HEADER, 2X2, 100  [HDR_THVT_2x2_100_M]
J9  HEADER, 3X21, 100  [HDR_THVT_3x21_100_M]
JP2  HEADER_1x2_100  [HDR_THVT_1x2_100_M]
JP3  HEADER_1x2_100  [HDR_THVT_1x2_100_M]
JP4  HEADER_1x2_100  [HDR_THVT_1x2_100_M]
JP5  HEADER_1x2_100  [HDR_THVT_1x2_100_M]
JP6  HEADER_1x2_100  [HDR_THVT_1x2_100_M]
JP7  HEADER_1x2_100  [HDR_THVT_1x2_100_M]
JP8  HEADER_1x2_100  [HDR_THVT_1x2_100_M]
Q1  DTC114EET1G  [SOT_416_3_63x31]
Q2  DTC114EET1G  [SOT_416_3_63x31]
Q3  DTC114EET1G  [SOT_416_3_63x31]
Q4  DTC114EET1G  [SOT_416_3_63x31]
Q5  DTC114EET1G  [SOT_416_3_63x31]
Q6  DTC114EET1G  [SOT_416_3_63x31]
Q7  DTC114EET1G  [SOT_416_3_63x31]
Q8  DTC114EET1G  [SOT_416_3_63x31]
Q9  DTC114EET1G  [SOT_416_3_63x31]
Q10  DTC114EET1G  [SOT_416_3_63x31]
Q11  DTC114EET1G  [SOT_416_3_63x31]
Q12  DTC114EET1G  [SOT_416_3_63x31]
Q13  DTC114EET1G  [SOT_416_3_63x31]
Q14  DTC114EET1G  [SOT_416_3_63x31]
Q15  DTC114EET1G  [SOT_416_3_63x31]
Q16  DTC114EET1G  [SOT_416_3_63x31]
Q17  DTC114EET1G  [SOT_416_3_63x31]
Q18  DTC114EET1G  [SOT_416_3_63x31]
Q19  DTC114EET1G  [SOT_416_3_63x31]
Q20  DTC114EET1G  [SOT_416_3_63x31]
R17  1k  [0402]
R18  604  [0402]
R19  604  [0402]
R20  1k  [0201]
R21  0  [0201]
R22  1k  [0402]
R23  1k  [0402]
R24  1k  [0402]
R25  1k  [0402]
R26  604  [0402]
R27  1k  [0402]
R28  1k  [0402]
R29  1k  [0402]
R302  49.9  [0201]
R303  49.9  [0201]
R304  49.9  [0201]
R305  49.9  [0201]
R309  49.9  [0201]
R310  49.9  [0201]
R311  49.9  [0201]
R312  49.9  [0201]
R313  49.9  [0201]
R314  49.9  [0201]
R315  49.9  [0201]
R316  49.9  [0201]
R317  49.9  [0201]
R318  49.9  [0201]
R319  49.9  [0201]
R320  49.9  [0201]
SHN2  SHUNT HEADER
SHN3  SHUNT HEADER
SHN4  SHUNT HEADER
SHN5  SHUNT HEADER
SHN8  SHUNT HEADER
SW1  AFE RESET  [sw_thvt_spst_pts635sl43]
Z_SH-H1  SHUNT-HEADER
Z_SH-H2  SHUNT-HEADER
Z_SH-H3  SHUNT-HEADER
Z_SH-H4  SHUNT-HEADER
Z_SH-H5  SHUNT-HEADER
Z_SH-H6  SHUNT-HEADER
Z_SH-H7  SHUNT-HEADER
Z_SH-H8  SHUNT-HEADER
Z_SH-H9  SHUNT-HEADER
Z_SH-H10  SHUNT-HEADER
Z_SH-H11  SHUNT-HEADER
Z_SH-H12  SHUNT-HEADER
Z_SH-H13  SHUNT-HEADER
Z_SH-H14  SHUNT-HEADER
Z_SH-H15  SHUNT-HEADER
Z_SH-H16  SHUNT-HEADER
Z_SH-H17  SHUNT-HEADER
Z_SH-H18  SHUNT-HEADER
Z_SH-H19  SHUNT-HEADER
Z_SH-H20  SHUNT-HEADER
Z_SH-H21  SHUNT-HEADER
Z_SH-H22  SHUNT-HEADER
Z_SH-H23  SHUNT-HEADER
Z_SH-H24  SHUNT-HEADER
Z_SH-H25  SHUNT-HEADER
Z_SH-H26  SHUNT-HEADER
Z_SH-H27  SHUNT-HEADER
Z_SH-H28  SHUNT-HEADER
Z_SH-H29  SHUNT-HEADER
Z_SH-H30  SHUNT-HEADER
Z_SH-H31  SHUNT-HEADER
Z_SH-H32  SHUNT-HEADER
Z_SH-H33  SHUNT-HEADER
Z_SH-H34  SHUNT-HEADER
Z_SH-H35  SHUNT-HEADER
Z_SH-H36  SHUNT-HEADER
Z_SH-H37  SHUNT-HEADER
Z_SH-H38  SHUNT-HEADER
Z_SH-H39  SHUNT-HEADER
Z_SH-H65  SHUNT-HEADER
Z_SH-H66  SHUNT-HEADER
sheet SHEET 05 - AFE
C49  0.1uF  [0201]
J10  HEADER, 3X5, 100  [HDR_THVT_3x5_100_M]
J11  HMTSW-105-07-G-D-.240  [HDR_THVT_2x5_100_M]
J12  HEADER, 2X8, 100  [HDR_THVT_2x8_100_M]
J13  HEADER, 3X8, 100  [HDR_THVT_3x8_100_M]
R30  100k  [0402]
R31  3.65k  [0201]
R32  0  [0402]
R33  0  [0402]
R34  0  [0402]
R35  0  [0402]
R36  0  [0402]
R37  0  [0402]
R38  0  [0402]
R39  0  [0402]
R40  0  [0402]
R41  0  [0402]
R42  0  [0402]
R43  0  [0402]
R44  0  [0402]
R45  0  [0402]
R46  0  [0402]
R47  0  [0402]
Z_SH-H40  SHUNT-HEADER
Z_SH-H41  SHUNT-HEADER
Z_SH-H42  SHUNT-HEADER
Z_SH-H43  SHUNT-HEADER
Z_SH-H44  SHUNT-HEADER
Z_SH-H45  SHUNT-HEADER
Z_SH-H46  SHUNT-HEADER
Z_SH-H47  SHUNT-HEADER
Z_SH-H48  SHUNT-HEADER
Z_SH-H49  SHUNT-HEADER
Z_SH-H50  SHUNT-HEADER
Z_SH-H51  SHUNT-HEADER
Z_SH-H52  SHUNT-HEADER
Z_SH-H53  SHUNT-HEADER
Z_SH-H54  SHUNT-HEADER
Z_SH-H55  SHUNT-HEADER
Z_SH-H56  SHUNT-HEADER
Z_SH-H57  SHUNT-HEADER
Z_SH-H58  SHUNT-HEADER
Z_SH-H59  SHUNT-HEADER
Z_SH-H60  SHUNT-HEADER
sheet SHEET 06 - AFE POWER
C50  10uF  [0603]
C51  1uF  [0204]
C52  .1uF  [0204]
C53  .1uF  [0204]
C54  .1uF  [0204]
C55  .1uF  [0204]
C56  .1uF  [0204]
C57  .1uF  [0204]
C58  .1uF  [0204]
C59  .1uF  [0204]
C60  .1uF  [0204]
C61  10uF  [0603]
C62  1uF  [0201]
C63  .1uF  [0204]
C64  .1uF  [0201]
C65  .1uF  [0201]
C66  10uF  [0603]
C67  1uF  [0204]
C68  .1uF  [0204]
C69  .1uF  [0204]
C70  .1uF  [0204]
C71  .1uF  [0204]
C72  .1uF  [0204]
C73  .1uF  [0204]
C74  .1uF  [0204]
C75  .1uF  [0204]
C76  10uF  [0603]
C77  1uF  [0201]
C78  10uF  [0603]
C79  1uF  [0201]
C80  .1uF  [0201]
C81  10uF  [0603]
C82  1uF  [0204]
C83  .1uF  [0204]
C84  .1uF  [0204]
C85  .1uF  [0204]
C86  .1uF  [0204]
C87  .1uF  [0204]
C88  .1uF  [0204]
C89  .1uF  [0204]
C90  .1uF  [0204]
C91  10uF  [0603]
C92  1uF  [0201]
C93  10uF  [0603]
C94  1uF  [0201]
C95  10uF  [0603]
C96  1uF  [0204]
C97  10uF  [0603]
C98  1uF  [0201]
C99  10uF  [0603]
C100  1uF  [0201]
C101  10uF  [0603]
C102  1uF  [0201]
C103  .1uF  [0201]
C104  10uF  [0603]
C105  1uF  [0201]
C106  .1uF  [0201]
C107  10uF  [0603]
C108  1uF  [0201]
C109  .1uF  [0201]
C110  1uF  [0402]
C111  10uF  [0603]
C112  1uF  [0201]
C113  .1uF  [0201]
C114  10uF  [0603]
C115  1uF  [0201]
C116  .1uF  [0201]
C117  10uF  [0603]
C118  1uF  [0201]
C119  .1uF  [0201]
C120  .1uF  [0204]
C121  .1uF  [0204]
C122  10uF  [0603]
C123  1uF  [0201]
C124  .1uF  [0204]
C125  .1uF  [0201]
C126  .1uF  [0201]
C429  .1uF  [0201]
C430  .1uF  [0201]
C431  .1uF  [0201]
C459  .1uF  [0201]
C460  .1uF  [0201]
C461  .1uF  [0201]
C462  1uF  [0201]
C463  .1uF  [0204]
C464  .1uF  [0201]
C465  1uF  [0201]
U1  AFE74XX  [BGA_20x20_400_p8mm]  (sections A,B,C,D,E,F)
sheet SHEET 08 - RX INPUTS
C127  0 ohm  [0201]
C129  0 ohm  [0201]
C130  0 ohm  [0201]
C131  10pF  [0201]
C132  0.01uF  [0402]
C133  0 ohm  [0201]
C135  0.1uF  [0201]
C136  10pF  [0201]
C137  0.01uF  [0402]
C139  0.1uF  [0201]
C140  0 ohm  [0201]
C141  0 ohm  [0201]
C142  0 ohm  [0201]
C143  0 ohm  [0201]
C144  10pF  [0201]
C145  10pF  [0201]
C469  0 ohm  [0201]
C470  0 ohm  [0201]
C471  0.01uF  [0402]
C472  0 ohm  [0201]
C473  0 ohm  [0201]
C474  10pF  [0201]
C475  10pF  [0201]
C476  0.1uF  [0201]
C477  0 ohm  [0201]
C478  0 ohm  [0201]
C479  0.01uF  [0402]
C480  0 ohm  [0201]
C481  0 ohm  [0201]
C482  10pF  [0201]
C483  10pF  [0201]
C484  0.1uF  [0201]
J14  SMA, JACK, END LAUNCH  [SMA_SMEL_DUAL_PSF-S01_250x215]
J15  SMA, JACK, END LAUNCH  [SMA_SMEL_DUAL_PSF-S01_250x215]
J16  SMA, JACK, END LAUNCH  [SMA_SMEL_DUAL_PSF-S01_250x215]
J17  SMA, JACK, END LAUNCH  [SMA_SMEL_DUAL_PSF-S01_250x215]
L3  3.3nH  [0402]
L4  15nH  [0402]
L5  10nH  [0402]
L6  15nH  [0402]
L7  15nH  [0402]
L8  15nH  [0402]
L9  3.3nH  [0402]
L10  10nH  [0402]
L50  15nH  [0402]
L51  15nH  [0402]
L52  3.3nH  [0402]
L53  10nH  [0402]
L54  15nH  [0402]
L55  15nH  [0402]
L56  3.3nH  [0402]
L57  10nH  [0402]
R48  0 ohm  [0201]
R50  0  [0402]
R52  0  [0402]
R54  0  [0402]
R58  0 ohm  [0201]
R72  0  [0402]
R73  0 ohm  [0201]
R74  0  [0402]
R76  0  [0402]
R77  0 ohm  [0201]
R330  0  [0402]
R331  0  [0402]
R332  0  [0402]
R333  0 ohm  [0201]
R334  0 ohm  [0201]
R335  0  [0402]
R336  0  [0402]
R337  0  [0402]
R338  0 ohm  [0201]
R339  0 ohm  [0201]
R350  0  [0603]
R351  0  [0603]
R352  0  [0603]
R353  0  [0603]
R354  0  [0603]
R355  0  [0603]
R356  0  [0603]
R357  0  [0603]
T4  TCM2-672X+  [TFMR_6_160x150_50]
T5  TC1-1-43X+  [TFMR_5_150X150_50]
T6  TCM2-672X+  [TFMR_6_160x150_50]
T7  TC1-1-43X+  [TFMR_5_150X150_50]
T8  TCM2-672X+  [TFMR_6_160x150_50]
T9  TC1-1-43X+  [TFMR_5_150X150_50]
T10  TCM2-672X+  [TFMR_6_160x150_50]
T11  TC1-1-43X+  [TFMR_5_150X150_50]
sheet SHEET 20 - POWER SUPPLIES
C315  10uF  [0805]
C316  1.0uF  [0603]
C317  10uF  [0805]
C318  10uF  [0805]
C321  47uF  [1210]
C322  22uF  [1206]
C323  22uF  [1206]
C393  10uF  [0508]
C394  10uF  [0508]
C395  1uF  [0306]
C396  .1uF  [0204]
C397  .1uF  [0204]
C398  10uF  [0508]
C399  0.01uF  [0402]
C400  1uF  [0402]
C401  10uF  [0805]
C454  10uF  [0508]
D13  MBRA120  [DIODE_SM_DO_214AC]
FB18  27uF  [1206_BEAD_NFM31P]
FB33  27uF  [1206_BEAD_NFM31P]
L45  2.2uH  [IND_SM_XFL4015]
PP2  PROBE POINT  [PROBE_POINT_22PAD]
PP3  PROBE POINT  [PROBE_POINT_22PAD]
PP22  PROBE POINT  [PROBE_POINT_22PAD]
PP23  PROBE POINT  [PROBE_POINT_22PAD]
Q25  SiA517DJ  [SC70-6L_85X85]
R228  12.7k  [0402]
R229  0  [0402]
R232  25.5k  [0402]
R233  10k  [0402]
R267  0  [0402]
R268  0  [0402]
R269  25.5K  [0402]
R270  0  [0402]
R271  0  [0402]
R272  0  [0402]
R306  1M  [0402]
R307  1M  [0402]
R327  100k  [0402]
RS1  0.05  [0805]
RS6  0.05  [0805]
U13  TPS62160  [SON_DSG_8]
U15  INA193  [DBV5]
U25  TPS7A8300  [qfn20_rgw_p65pitch]
U26  INA193  [DBV5]
sheet SHEET 21 - HARDWARE
CONN HOUS 2POS .100  Mating Connector for J38
HS1  HEAT SINK  [HEATSINK_27X27mm_ATS]
J38  HEADER 2POS, FAN POWER  [hdr_thvt_1x2_100_m]
MT1  STANDOFF,  4-40, 3/16 Rd x 1 3/16 Length, ALUM  [MFG125_PLATED]
MT2  STANDOFF,  4-40, 3/16 Rd x 1 3/16 Length, ALUM  [MFG125_PLATED]
MT3  STANDOFF,  4-40, 3/16 Rd x 1 3/16 Length, ALUM  [MFG125_PLATED]
MT4  STANDOFF,  4-40, 3/16 Rd x 1 3/16 Length, ALUM  [MFG125_PLATED]
MT5  STANDOFF,  4-40, 3/16 Rd x 1 3/16 Length, ALUM  [MFG125_PLATED]
MT6  STANDOFF,  4-40, 3/16 Rd x 1 3/16 Length, ALUM  [MFG125_PLATED]
SHIELD1  4T4R_TX_SHIELD  [4T4R_TX_SHIELD]
SHIELD2  4T4R_TX_SHIELD  [4T4R_TX_SHIELD]
SHIELD3  4T4R_TX_SHIELD  [4T4R_TX_SHIELD]
SHIELD4  4T4R_TX_SHIELD  [4T4R_TX_SHIELD]
SHIELD5  4T4R_RX_SHIELD  [4T4R_RX_SHIELD]
SHIELD6  4T4R_RX_SHIELD  [4T4R_RX_SHIELD]
SHIELD7  4T4R_RX_SHIELD  [4T4R_RX_SHIELD]
SHIELD8  4T4R_RX_SHIELD  [4T4R_RX_SHIELD]
Z_FANHEATSINK1  FAN FOR HEATSINK
Z_PCB1  PCB, AFE74XX
Z_SCREW1  SCREW, PHIL, 4-40x3/8", SS
Z_SCREW2  SCREW, PHIL, 4-40x3/8", SS
Z_SCREW3  SCREW, PHIL, 4-40x3/8", SS
Z_SCREW4  SCREW, PHIL, 4-40x3/8", SS
Z_SCREW5  SCREW, PHIL, 4-40x3/8", SS
Z_SCREW6  SCREW, PHIL, 4-40x3/8", SS

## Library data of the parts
C1 C4 C7 C132 C137 C399 C471 C479 = CAP_NP_1: Mfr_Name: MURATA; Mfr_Part_Number: GCM155R71H103KA55J; TOL: 10%; VOLTAGE: 50V
C2 C3 C6 C9-C40 = CAP0402_0: Mfr_Name: ATC; Mfr_Part_Number: 531Z104KTR8; TOL: 10%; Voltage: 10V
J1 = TMP_0: Mfr_Name: Johnson Components; Mfr_Part_Number: 142-0711-841; TI_Silktext: AFECLK
J2 = SMP_PLUG_SMT: TI_Silktext: EXT_CLKP
J3 = TMP_0: Mfr_Name: Johnson Components; Mfr_Part_Number: 142-0711-841; TI_Silktext: CLKTXP
J4 = SMP_PLUG_SMT: TI_Silktext: EXT_CLKN
J5 = SMP_PLUG_SMT: TI_Silktext: EXT_SYSREFP
J6 = SMP_PLUG_SMT: TI_Silktext: EXT_SYSREFN
L1 L2 = CHOKE: Mfr_Name: Coilcraft; Mfr_Part_Number: 0402HP-20NXGLU
R1 R4 R8 R54 R76 R332 R337 = Res_0603_Zero_H: Mfr_Part_Number: ERJ-2GE0R00X
R2 R7 R9 = Res_0402_49.9: Mfr_Part_Number: ERJ-2RKF49R9X; Note: DNI
R3 R10 R11 R14 R40-R47 R50 R52 R72 R74 R330 R331 R335 R336 = Res_0603_Zero_H: Mfr_Part_Number: ERJ-2GE0R00X; Note: DNI
R5 R295 R296 = Res_0402_Zero_H_DNI: Mfr_Part_Number: ERJ-1GNJ101C; Note: DNI
R6 = Res_0402_49.9: Mfr_Name: VISHAY DALE; Mfr_Part_Number: CRCW020149R9FKED; Note: DNI; TOL: 1%; Wattage: 1/20W
R12 R13 = R: Mfr_Name: PANASONIC; Mfr_Part_Number: ERJ-1GN0R00C; TOL: 5%
R302-R305 R309-R320 R322 R323 = Res_0402_49.9: Mfr_Name: VISHAY DALE; Mfr_Part_Number: CRCW020149R9FKED; TOL: 1%; Wattage: 1/20W
T1 = TFMR_6_TCM2-43X+: Impedance Ratio: 2:1; Mfr_Part_Number: TCM2-43X-2+
T2 T3 = BALUN_NCR2-113+: Mfr_Part_Number: NCR2-113-2+
C41-C48 = CAP_0402_0.001uF_H
D1 = LED: CLASS: DISCRETE; Mfr_Name: PANASONIC; Mfr_Part_Number: LNJ437W84RA; TI_SILKTEXT: PLLREFLD
D2 = LED: CLASS: DISCRETE; Mfr_Name: PANASONIC; Mfr_Part_Number: LNJ437W84RA; TI_SILKTEXT: PLLCLKLD
D3 = LED: CLASS: DISCRETE; Mfr_Name: PANASONIC; Mfr_Part_Number: LNJ437W84RA; TI_SILKTEXT: COMMON ALARM
J7 = HEADER_3x18_100: Note: SHORT 1-2,4-5,7-8,10-11,13-14,16-17,19-20,22-23,25-26,28-29,31-32,34-35, 37-38,40-41,43-44,46-47,49-50,52-53; TI_SILKTEXT: ALARM OUT
J8 = HEADER_2x2_100: Mfr_Part_Number: HTSW-102-07-G-D; Note: SHORT 1-2,3-4; TI_SILKTEXT: PLL STATUS
J9 = HEADER_3x21_100: Note: SHORT 1-2,4-5,7-8,10-11,13-14,16-17,19-20,22-23,25-26,28-29,31-32,34-35, 37-38,40-41,43-44,46-47,49-50,52-53,56-57,59-60,61-62; TI_SILKTEXT: AFE CONTROL
JP2-JP5 JP8 = HDR_2x1_100: Mfr_Part_Number: HTSW-102-07-G-S; Note: SHUNT 1-2
JP6 JP7 = HDR_2x1_100: Mfr_Part_Number: HTSW-102-07-G-S; Note: OPEN
Q1-Q20 = MMBT2222A: Mfr_Name: ON Semiconductor
R17 R22-R25 R27-R29 = R_0: Mfr_Name: Panasonic; Mfr_Part_Number: ERJ-2RKF1001X; PART_NUMBER: Panasonic ERJ-2RKF1001X; TOL: 1%
R18 R19 R26 = R: Mfr_Name: PANASONIC; Mfr_Part_Number: ERJ-2RKF6040X; TOL: 1%; VOLTAGE: 1/10W
R20 = R_0: Mfr_Name: PANASONIC; Mfr_Part_Number: ERJ-1GNF1001C; TOL: 1%
R21 = Res_0603_Zero_H: Mfr_Part_Number: ERJ-1GN0R00C; Note: DNI
SHN2-SHN5 SHN8 = SHUNT_HEADER: Mfr_Name: TE CONNECTIVITY; Mfr_Part_Number: 1-382811-6
SW1 = SW_PUSHBUTTON: Mfr_Name: C&K Components; Mfr_Part_Number: PTS635SL43 LFS
Z_SH-H1-Z_SH-H60 Z_SH-H65 Z_SH-H66 = SHUNT-2PINHEADER: Mfr_Name: TE CONNECTIVITY; Mfr_Part_Number: 1-382811-6
C49 C135 C139 C476 C484 = CAP_0402_0.01uF_H: Mfr_Name: TDK; Mfr_Part_Number: C0603X7S1A104K030BC; TOL: 10%; VOLTAGE: 10V
J10 = HEADER_3x5_100: Mfr_Part_Number: HTSW-105-07-G-T; Note: SHORT 1-2,4-5,7-8,10-11,13-14; TI_SILKTEXT: JTAG
J11 = HEADER_2x5_100: Mfr_Part_Number: HTSW-105-07-G-D; TI_SILKTEXT: <TI_SILKTEXT>
J12 = HEADER_2x8_100: Mfr_Part_Number: HTSW-108-07-G-D; Note: SHORT 1-2,3-4,5-6,7-8,9-10,11-12,13-14,15-16; TI_SILKTEXT: FSPI
J13 = HEADER_3x8_100: Mfr_Part_Number: HTSW-108-07-G-T; TI_SILKTEXT: SPI
R30 = Res_0402_1k: Mfr_Part_Number: ERJ-2RKF1003X
R31 = R_1: CLASS: DISCRETE; Mfr_Name: PANASONIC; Mfr_Part_Number: ERJ-1GNF3651C; TOL: 1%
R32-R39 = R: Mfr_Name: PANASONIC; Mfr_Part_Number: ERJ-2GE0R00X; TOL: 5%
C50 C61 C66 C76 C78 C81 C91 C93 C95 C97 C99 C101 C104 C107 C111 C114 C117 C122 = CAP0201_0: CLASS: DISCRETE; Mfr_Name: TDK CORP; Mfr_Part_Number: C1608X7S0J106M080AC; TOL: 20%; VOLTAGE: 6.3V
C51 C67 C82 C96 = CAP0201_0: CLASS: DISCRETE; Mfr_Name: Taiyo Yuden; Mfr_Part_Number: JWK105BJ105MP-F; TOL: 20%; VOLTAGE: 6.3V
C52-C60 C63 C68-C75 C83-C90 C120 C121 C124 C396 C397 C463 = CAP0402_0: Mfr_Name: Murata; Mfr_Part_Number: LLL153C80J104ME01E; TOL: 20%; Voltage: 6.3V
C62 C77 C79 C92 C94 C98 C100 C102 C105 C108 C112 C115 C118 C123 C462 C465 = CAP0201_0: CLASS: DISCRETE; Mfr_Name: Samsung; Mfr_Part_Number: CL03A105KQ3CSNC; TOL: 10%; VOLTAGE: 6.3V
C64 C65 C80 C103 C106 C109 C113 C116 C119 C125 C126 C429-C431 C459-C461 C464 = CAP0402_0: Mfr_Name: Murata; Mfr_Part_Number: GRM033R61A104KE15D; TOL: 10%; Voltage: 10V
C110 C400 = CAP0201_0: CLASS: DISCRETE; Mfr_Name: Murata; Mfr_Part_Number: GRM153R61A105ME95D; TOL: 10%; VOLTAGE: 10V
U1 = AFE768x: Mfr_Part_Number: AFE7444IABJ
C127 C133 C140 C141 C469 C470 C477 C478 = CAP_0402_0.01uF_H: Mfr_Name: Panasonic; Mfr_Part_Number: ERJ-1GN0R00C
C129 C130 C142 C143 C472 C473 C480 C481 = CAP_0603_0.1uF_H: Mfr_Name: Panasonic; Mfr_Part_Number: ERJ-1GN0R00C
C131 C136 C144 C145 C474 C475 C482 C483 = CAP_0603_0.1uF_H: Mfr_Name: Murata; Mfr_Part_Number: GJM0336C1E100GB01D; TOL: 2%; Voltage: 25V
J14 = SMA-END_PLUG_ROUND_0: Mfr_Name: Johnson Components; Mfr_Part_Number: 142-0711-821; TI_Silktext: AIN1
J15 = SMA-END_PLUG_ROUND_0: Mfr_Name: Johnson Components; Mfr_Part_Number: 142-0711-821; TI_Silktext: AIN2
J16 = SMA-END_PLUG_ROUND_0: Mfr_Name: Johnson Components; Mfr_Part_Number: 142-0711-821; TI_Silktext: BIN1
J17 = SMA-END_PLUG_ROUND_0: Mfr_Name: Johnson Components; Mfr_Part_Number: 142-0711-821; TI_Silktext: BIN2
L3 L9 L52 L56 = CHOKE: Mfr_Name: Coilcraft; Mfr_Part_Number: 0402HP-3N3XGLU; Note: DNI
L4 L6-L8 L50 L51 L54 L55 = CHOKE: Mfr_Name: Coilcraft; Mfr_Part_Number: 0402HP-15NXGLU; Note: DNI
L5 L10 L53 L57 = CHOKE: Mfr_Name: Coilcraft; Mfr_Part_Number: 0402HP-10NXGLU; Note: DNI
R48 R58 R73 R77 R333 R334 R338 R339 = Res_0402_Zero_H_DNI: Mfr_Name: Panasonic; Mfr_Part_Number: ERJ-1GN0R00C
R350-R357 = Res_0603_Zero_DNI: Mfr_Part_Number: ERJ-3GEY0R00V
T4 T6 T8 T10 = BALUN_TCM2-672X+: Mfr_Part_Number: TCM2-672X-1+
T5 T7 T9 T11 = BALUN_TC1-1-43X+: Mfr_Part_Number: TC1-1-43X-2+; Note: DNI
C315 C317 C318 C401 = CAP_NP_1: Mfr_Name: SAMSUNG; Mfr_Part_Number: CL21B106KOQNNNE; TOL: 10%; VOLTAGE: 16V
C316 = CAP_NP_0: Mfr_Name: Samsung Electro-Mechanics America, Inc; Mfr_Part_Number: CL10B105KO8NNNC; TOL: 10%; VOLTAGE: 16V
C321 = CAP_NP_0: Mfr_Name: MURATA; Mfr_Part_Number: GRM32ER71A476KE15L; TOL: 10%; VOLTAGE: 10V
C322 C323 = CAP_1210_22uF: Mfr_Name: MURATA; Mfr_Part_Number: GRM31CR71A226KE15L
C393 C394 C398 C454 = CAP_NP_1: Mfr_Name: Taiyo Yuden; Mfr_Part_Number: LWK212BJ106MD-T; TOL: 20%; VOLTAGE: 10V
C395 = CAP0201_0: CLASS: DISCRETE; Mfr_Name: Samsung; Mfr_Part_Number: C0816X5R1C105M050AC; TOL: 20%; VOLTAGE: 16V
D13 = DIODE_SCHOTTKY: Mfr_Name: ON Semi; Mfr_Part_Number: MBRA120ET3G
FB18 FB33 = BEAD_NFM31P: Mfr_Name: Murata; Mfr_Part_Number: NFM31PC276B0J3L; Tolerance: 20%
L45 = CHOKE: Mfr_Name: Wurth; Mfr_Part_Number: 744025002
PP2 = PROBE_POINT_0: Mfr_Name: Harwin; Mfr_Part_Number: P1113SS3; Note: DNI; TI_Silktext: -1.8V_VEE
PP3 PP23 = PROBE_POINT_0: Mfr_Name: Harwin; Mfr_Part_Number: P1113SS3; Note: DNI; TI_Silktext: <TI_Silktext>
PP22 = PROBE_POINT_0: Mfr_Name: Harwin; Mfr_Part_Number: P1113SS3; Note: DNI; TI_Silktext: +1.8V_VDDIO
Q25 = MOSFET_SiA517DJ
R228 = R_1: CLASS: DISCRETE; Mfr_Name: Panasonic; Mfr_Part_Number: ERJ-2RKF1272X; TOL: 1%
R229 R267 R268 R271 R272 = R: Mfr_Name: Panasonic; Mfr_Part_Number: ERJ-2GE0R00X; TOL: 5%
R232 R269 = R_1: CLASS: DISCRETE; Mfr_Name: Vishay Dale; Mfr_Part_Number: CRCW040225K5FKED; TOL: 1%
R233 = R_1: CLASS: DISCRETE; Mfr_Name: Panasonic; Mfr_Part_Number: ERJ-2RKF1002X; TOL: 1%
R270 = R: Mfr_Name: Panasonic; Mfr_Part_Number: ERJ-2GE0R00X; Note: DNI; TOL: 5%
R306 R307 = Res_0402_1k: Mfr_Part_Number: ERJ-2RKF1004X
R327 = R: Mfr_Name: Panasonic; Mfr_Part_Number: ERJ-2RKF1003X; TOL: 1%
RS1 RS6 = R: Mfr_Name: Vishay Dale; Mfr_Part_Number: WSL0805R0500FEA18; Note: Rs; TOL: 1%
U13 = TPS6217x_SON8: Mfr_Name: Texas Instruments; Mfr_Part_Number: TPS62160DSGR
U15 U26 = INA138: Mfr_Name: Texas Instruments; Mfr_Part_Number: INA193AIDBVT
U25 = TPS7A8300: Mfr_Part_Number: TPS7A8300RGWR
CONN HOUS 2POS .100 = MechPart: Distributed by: Digi Key; Distributor Part #: 277-1011-ND; Mfr_Name: Molex; Mfr_Part_Number: 22-01-3027; Note: For fan wires assembly; use crimp terminal 0008500114
HS1 = HEATSINK_1: Mfr_Name: Advanced Thermal Solutions; Mfr_Part_Number: ATS-1846-C1-R0; Note: use fan SUNON MC25060V1-000U-A99
J38 = HEADER_2_SM: Mfr_Name: Molex; Mfr_Part_Number: 0022112022
MT1-MT6 = MOUNTING_HOLE: Mfr_Name: RAF Electronic Hardware; Mfr_Part_Number: 1648-440-AL
SHIELD1-SHIELD4 = 4T4R_TX_SHIELD: Mfr_Name: Leader Tech; Mfr_Part_Number: SL-12629
SHIELD5-SHIELD8 = 4T4R_RX_SHIELD: Mfr_Name: Leader Tech; Mfr_Part_Number: SL-12628
Z_FANHEATSINK1 = HEATSINK: Mfr_Name: SUNON; Mfr_Part_Number: MC25060V1-000U-A99
Z_PCB1 = BARE_BOARD: Mfr_Name: ANY VENDOR; Mfr_Part_Number: AFE74XXEVM REV D
Z_SCREW1-Z_SCREW6 = STANDOFF-SCREW

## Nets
+1.8V_RX_PWR_SENSE: C399.2 FB33.1 RS6.1 U25.2(SNS) U26.4(VIN-)
+2.2V: C393.1 C396.1 R327.1 U25.15(IN1) U25.16(IN2) U25.17(IN3) ; also on sheet 18 19 20
+5VIN: C315.1 C317.1 D1.1(ANODE) D2.1(ANODE) D3.1(ANODE) J38.1 Q25.4(S2) R306.2 U13.2(VIN) U15.5(V+) U26.5(V+) ; also on sheet 16 18 19 20 21
-1.8V: C317.2 C321.1 C322.1 C323.1 D13.1(ANODE) R233.1 R307.2 RS1.2 U13.1(PGND) U13.4(AGND) U13.9(PWRPAD) U15.4(VIN-)
DVDD: C50.1 C51.1 C52.1 C53.1 C54.1 C55.1 C56.1 C57.1 C58.1 C59.1 C60.1 C120.1 C121.1 U1.G13(DVDD) U1.H6(DVDD) U1.H7(DVDD) U1.H13(DVDD) U1.J12(DVDD) U1.J13(DVDD) U1.K6(DVDDPR) U1.K7(DVDDPR) U1.K8(DVDDAR) U1.K9(DVDD) U1.K10(VPP) U1.K11(DVDD) U1.K12(DVDD) U1.K13(DVDD) U1.L6(DVDD) U1.L7(VNWA) U1.L8(DVDD) U1.L9(DVDD) U1.L10(DVDD) U1.L11(DVDD) U1.L12(DVDD) U1.L13(DVDD) U1.M12(DVDD) U1.M13(DVDD) U1.N6(DVDD) U1.N7(DVDD) U1.N13(DVDD) U1.P13(DVDD) ; also on sheet 18
GND: C41.2 C49.2 C50.2 C51.2 C52.2 C53.2 C54.2 C55.2 C56.2 C57.2 C58.2 C59.2 C60.2 C61.2 C62.2 C63.2 C64.2 C65.2 C66.2 C67.2 C68.2 C69.2 C70.2 C71.2 C72.2 C73.2 C74.2 C75.2 C76.2 C77.2 C78.2 C79.2 C80.2 C81.2 C82.2 C83.2 C84.2 C85.2 C86.2 C87.2 C88.2 C89.2 C90.2 C91.2 C92.2 C93.2 C94.2 C95.2 C96.2 C97.2 C98.2 C99.2 C100.2 C101.2 C102.2 C103.2 C104.2 C105.2 C106.2 C107.2 C108.2 C109.2 C110.2 C111.2 C112.2 C113.2 C114.2 C115.2 C116.2 C117.2 C118.2 C119.2 C120.2 C121.2 C122.2 C123.2 C124.2 C125.2 C126.2 C135.1 C139.1 C315.2 C316.2 C318.2 C321.2 C322.2 C323.2 C393.2 C394.2 C395.2 C396.2 C397.2 C398.2 C400.2 C401.2 C429.2 C430.2 C431.2 C454.2 C459.2 C460.2 C461.2 C462.2 C463.2 C464.2 C465.2 C476.1 C484.1 D13.2(CATHODE) FB18.2 FB33.2 HS1.MTG1 HS1.MTG2 J1.2(GND) J1.3(GND) J1.4(GND) J1.5(GND) J2.2(SHIELD1) J3.2(GND) J3.3(GND) J3.4(GND) J3.5(GND) J4.2(SHIELD1) J5.2(SHIELD1) J6.2(SHIELD1) J9.55 J9.58 J9.61 J11.2 J11.4 J11.6 J11.8 J11.10 J14.2(SHIELD3) J14.3(SHIELD4) J14.4(SHIELD1) J14.5(SHIELD2) J15.2(SHIELD3) J15.3(SHIELD4) J15.4(SHIELD1) J15.5(SHIELD2) J16.2(SHIELD3) J16.3(SHIELD4) J16.4(SHIELD1) J16.5(SHIELD2) J17.2(SHIELD3) J17.3(SHIELD4) J17.4(SHIELD1) J17.5(SHIELD2) J38.2 L4.1 L6.1 L7.1 L8.1 L45.2 L50.1 L51.1 L54.1 L55.1 MT1.1 MT2.1 MT3.1 MT4.1 MT5.1 MT6.1 Q1.2(E) Q2.2(E) Q3.2(E) Q4.2(E) Q5.2(E) Q6.2(E) Q7.2(E) Q8.2(E) Q9.2(E) Q10.2(E) Q11.2(E) Q12.2(E) Q13.2(E) Q14.2(E) Q15.2(E) Q16.2(E) Q17.2(E) Q18.2(E) Q19.2(E) Q20.2(E) Q25.1(S1) R2.2 R6.1 R7.2 R9.2 R20.2 R22.2 R23.2 R24.2 R25.2 R27.2 R28.2 R29.2 R30.2 R31.1 R50.1 R52.1 R72.1 R74.1 R228.2 R232.2 R269.2 R270.1 R271.1 R272.1 R330.1 R331.1 R335.1 R336.1 SHIELD1.MT1 SHIELD1.MT2 SHIELD1.MT3 SHIELD2.MT1 SHIELD2.MT2 SHIELD2.MT3 SHIELD3.MT1 SHIELD3.MT2 SHIELD3.MT3 SHIELD4.MT1 SHIELD4.MT2 SHIELD4.MT3 SHIELD5.MT1 SHIELD5.MT2 SHIELD5.MT3 SHIELD5.MT4 SHIELD6.MT1 SHIELD6.MT2 SHIELD6.MT3 SHIELD6.MT4 SHIELD7.MT1 SHIELD7.MT2 SHIELD7.MT3 SHIELD7.MT4 SHIELD8.MT1 SHIELD8.MT2 SHIELD8.MT3 SHIELD8.MT4 SW1.1 T1.1(primary1_GND) T1.2(primary2_GND) T2.1(GND1) T2.3(GND2) T2.5(GND3) T3.1(GND1) T3.3(GND2) T3.5(GND3) T4.1(NC) T4.2(PRI/GND) T6.1(NC) T6.2(PRI/GND) T8.1(NC) T8.2(PRI/GND) T10.1(NC) T10.2(PRI/GND) U1.A1(VSST) U1.A4(VSST) U1.A5(RXAGND) U1.A6(RXAGND) U1.A9(RXAGND) U1.A12(RXAGND) U1.A15(RXAGND) U1.A18(RXAGND) U1.A19(VSSATXAB) U1.A20(VSSATXAB) U1.B2(VSST) U1.B3(VSST) U1.B4(VSST) U1.B5(RXAGND) U1.B6(RXAGND) U1.B7(RXAGND) U1.B8(RXAGND) U1.B9(RXAGND) U1.B10(RXAGND) U1.B11(RXAGND) U1.B12(RXAGND) U1.B13(RXAGND) U1.B14(RXAGND) U1.B15(RXAGND) U1.B16(RXAGND) U1.B17(RXAGND) U1.B18(RXAGND) U1.B19(VSSATXAB) U1.C2(VSST) U1.C19(VSSATXAB) U1.D1(VSST) U1.D2(VSST) U1.D19(VSSATXAB) U1.D20(VSSATXAB) U1.E2(VSST) U1.E19(VSSATXAB) U1.E20(VSSATXAB) U1.F2(VSST) U1.F12(DGND) U1.F13(DGND) U1.F16(VSSATXAB) U1.F17(VSSATXAB) U1.F18(VSSATXAB) U1.F19(VSSATXAB) U1.G1(VSST) U1.G2(VSST) U1.G12(DGND) U1.G19(VSSATXAB) U1.H2(VSST) U1.H12(DGND) U1.H19(VSSATXAB) U1.H20(VSSATXAB) U1.J2(VSST) U1.J6(DGND) U1.J7(DGND) U1.J8(DGND) U1.J9(DGND) U1.J10(DGND) U1.J11(DGND) U1.J16(VSSCLK) U1.J17(VSSCLK) U1.J18(VSSCLK) U1.J19(VSSCLK) U1.J20(VSSCLK) U1.K1(VSST) U1.K3(VSST) U1.K4(VSST) U1.K20(VSSCLK) U1.L1(VSST) U1.L3(VSST) U1.L4(VSST) U1.L16(VSSCLK) U1.L20(VSSCLK) U1.M2(VSST) U1.M6(DGND) U1.M7(DGND) U1.M8(DGND) U1.M9(DGND) U1.M10(DGND) U1.M11(DGND) U1.M16(VSSCLK) U1.M18(VSSCLK) U1.M19(VSSCLK) U1.M20(VSSCLK) U1.N2(VSST) U1.N12(DGND) U1.N19(VSSATXCD) U1.N20(VSSATXCD) U1.P1(VSST) U1.P2(VSST) U1.P12(DGND) U1.P19(VSSATXCD) U1.R2(VSST) U1.R12(DGND) U1.R13(DGND) U1.R16(VSSATXCD) U1.R17(VSSATXCD) U1.R18(VSSATXCD) U1.R19(VSSATXCD) U1.T2(VSST) U1.T19(VSSATXCD) U1.T20(VSSATXCD) U1.U1(VSST) U1.U2(VSST) U1.U19(VSSATXCD) U1.U20(VSSATXCD) U1.V2(VSST) U1.V19(VSSATXCD) U1.W2(VSST) U1.W3(VSST) U1.W4(VSST) U1.W5(RXAGND) U1.W6(RXAGND) U1.W7(RXAGND) U1.W8(RXAGND) U1.W9(RXAGND) U1.W10(RXAGND) U1.W11(RXAGND) U1.W12(RXAGND) U1.W13(RXAGND) U1.W14(RXAGND) U1.W15(RXAGND) U1.W16(RXAGND) U1.W17(RXAGND) U1.W18(RXAGND) U1.W19(VSSATXCD) U1.Y1(VSST) U1.Y4(VSST) U1.Y5(RXAGND) U1.Y6(RXAGND) U1.Y9(RXAGND) U1.Y12(RXAGND) U1.Y15(RXAGND) U1.Y18(RXAGND) U1.Y19(VSSATXCD) U1.Y20(VSSATXCD) U13.6(VOS) U15.2(GND) U25.8(GND) U25.18(GND) U25.21(THERMPAD) U26.2(GND) ; also on sheet 11 12 13 14 15 16 18 19 20 21
VDDA_1.0V: C76.1 C77.1 C429.1 U1.F15(VDDATXAB) U1.R15(VDDATXCD) ; also on sheet 19
VDDA_1.8V: C78.1 C79.1 C80.1 U1.G18(VDDA18TXAB) U1.H18(VDDA18TXAB) U1.N18(VDDA18TXCD) U1.P18(VDDA18TXCD) ; also on sheet 12 13 20
VDDA_SERDES_1.0V: C114.1 C115.1 C116.1 U1.D3(VDDA) U1.D4(VDDA) U1.U3(VDDA) U1.U4(VDDA) ; also on sheet 19
VDDCLK_1.0V: C107.1 C108.1 C109.1 C431.1 U1.G16(VDDCLK) U1.H16(VDDCLK) U1.K17(VDDCLK) U1.N16(VDDCLK) U1.P16(VDDCLK) ; also on sheet 19
VDDE: C122.1 C123.1 C124.1 C125.1 C126.1 C459.1 C460.1 U1.F14(VDDETXAB) U1.G14(VDDETXAB) U1.H14(VDDETXAB) U1.J14(VDDETXAB) U1.M14(VDDETXCD) U1.N14(VDDETXCD) U1.P14(VDDETXCD) U1.R14(VDDETXCD) ; also on sheet 18
VDDGPIO_1.8V: C42.1 C43.1 C44.1 C45.1 C46.1 C47.1 C48.1 C110.1 J9.57 J9.60 J9.63 JP2.2 JP3.2 JP4.2 JP5.2 JP6.2 JP7.2 JP8.2 R17.1 U1.D17(VDDGPIO18) ; also on sheet 20
VDDL1_1.0V: C104.1 C105.1 C106.1 C464.1 C465.1 U1.G15(VDDL1TXAB) U1.H15(VDDL1TXAB) U1.N15(VDDL1TXCD) U1.P15(VDDL1TXCD) ; also on sheet 19
VDDL2_1.0V: C101.1 C102.1 C103.1 C461.1 C462.1 U1.G17(VDDL2TXAB) U1.H17(VDDL2TXAB) U1.N17(VDDL2TXCD) U1.P17(VDDL2TXCD) ; also on sheet 19
VDDPLL_1.0V: C91.1 C92.1 U1.K18(VDDPLL) ; also on sheet 19
VDDPLL_1.8V: C93.1 C94.1 U1.L18(VDDAPLL18) ; also on sheet 20
VDDR_SERDES_1.5V: C111.1 C112.1 C113.1 U1.F3(VDDR) U1.F4(VDDR) U1.R3(VDDR) U1.R4(VDDR) ; also on sheet 20
VDDT_SERDES_1.0V: C117.1 C118.1 C119.1 U1.H3(VDDT) U1.H4(VDDT) U1.N3(VDDT) U1.N4(VDDT) ; also on sheet 19
VDDTX_1.0V: C99.1 C100.1 U1.J15(VDDTX) ; also on sheet 19
VDDTX_1.8V: C97.1 C98.1 U1.K16(VDDTX18) ; also on sheet 20
VDDVCO_1.8V: C95.1 C96.1 U1.L17(VDDAVCO18) U1.M17(VDDAVCO18) ; also on sheet 20
VEE: C61.1 C62.1 C63.1 C64.1 C65.1 C316.1 C318.1 C430.1 C463.1 FB18.3 PP2.1 U1.D18(VEETXAB) U1.E17(VEETXAB) U1.E18(VEETXAB) U1.T17(VEETXCD) U1.T18(VEETXCD) U1.U17(VEETXCD)
A_IN1: J14.1(CENTER) R50.2 R54.1
A_IN2: J15.1(CENTER) R330.2 R332.1
ADC_ALT_SYNC_N: U1.N10(syncbinm1) ; also on sheet 16
ADC_ALT_SYNC_P: U1.N11(syncbinp1) ; also on sheet 16
ADC_SYNC_N: U1.H10(syncbinm0) ; also on sheet 16
ADC_SYNC_P: U1.H11(syncbinp0) ; also on sheet 16
AIN1: C132.2 L7.2 T4.3(PRI_DOT)
AIN1M: C136.1 U1.A16(RXADSA1M)
AIN1P: C131.1 U1.A17(RXADSA1P)
AIN2: C471.2 L51.2 T6.3(PRI_DOT)
AIN2M: C475.1 U1.A13(RXADSA2M)
AIN2P: C474.1 U1.A14(RXADSA2P)
ALARM_TX1: J7.1 Q3.1(B)
ALARM_TX2: J7.4 Q4.1(B)
ALARMTX1: J7.2 U1.C17(TXALARM1)
ALARMTX2: J7.5 U1.V17(TXALARM2)
B_IN1: J16.1(CENTER) R72.2 R76.1
B_IN2: J17.1(CENTER) R335.2 R337.1
BIN1: C137.2 L8.2 T8.3(PRI_DOT)
BIN1M: C145.1 U1.A10(RXBDSA1M)
BIN1P: C144.1 U1.A11(RXBDSA1P)
BIN2: C479.2 L55.2 T10.3(PRI_DOT)
BIN2M: C483.1 U1.A7(RXBDSA2M)
BIN2P: C482.1 U1.A8(RXBDSA2P)
CIN1M: U1.Y16(RXCDSA1M) ; also on sheet 11
CIN1P: U1.Y17(RXCDSA1P) ; also on sheet 11
CIN2M: U1.Y13(RXCDSA2M) ; also on sheet 11
CIN2P: U1.Y14(RXCDSA2P) ; also on sheet 11
CLK_N: L2.1 R295.1 R323.1 U1.L19(CLKM)
CLK_P: L1.1 R295.2 R322.1 U1.K19(CLKP)
CLKN: L2.2 ; also on sheet 14
CLKP: L1.2 ; also on sheet 14
DAC_ALT_SYNC_N: U1.P10(syncboutm1) ; also on sheet 16
DAC_ALT_SYNC_P: U1.P11(syncboutp1) ; also on sheet 16
DAC_SYNC_N: U1.G10(syncboutm0) ; also on sheet 16
DAC_SYNC_P: U1.G11(syncboutp0) ; also on sheet 16
DACCLK_IN: C4.1 J1.1(CENTER)
DACOUT: R21.2 ; also on sheet 18
DIN1M: U1.Y10(RXDDSA1M) ; also on sheet 11
DIN1P: U1.Y11(RXDDSA1P) ; also on sheet 11
DIN2M: U1.Y7(RXDDSA2M) ; also on sheet 11
DIN2P: U1.Y8(RXDDSA2P) ; also on sheet 11
DIV_IN: C1.2 ; also on sheet 14
DP0_C2M_N: C37.1 ; also on sheet 16
DP0_C2M_P: C39.1 ; also on sheet 16
DP0_M2C_N: C35.1 ; also on sheet 16
DP0_M2C_P: C36.1 ; also on sheet 16
DP1_C2M_N: C33.1 ; also on sheet 16
DP1_C2M_P: C34.1 ; also on sheet 16
DP1_M2C_N: C38.1 ; also on sheet 16
DP1_M2C_P: C40.1 ; also on sheet 16
DP2_C2M_N: C31.1 ; also on sheet 16
DP2_C2M_P: C29.1 ; also on sheet 16
DP2_M2C_N: C32.1 ; also on sheet 16
DP2_M2C_P: C30.1 ; also on sheet 16
DP3_C2M_N: C26.1 ; also on sheet 16
DP3_C2M_P: C25.1 ; also on sheet 16
DP3_M2C_N: C27.1 ; also on sheet 16
DP3_M2C_P: C28.1 ; also on sheet 16
DP4_C2M_N: C19.1 ; also on sheet 16
DP4_C2M_P: C17.1 ; also on sheet 16
DP4_M2C_N: C20.1 ; also on sheet 16
DP4_M2C_P: C18.1 ; also on sheet 16
DP5_C2M_N: C10.1 ; also on sheet 16
DP5_C2M_P: C9.1 ; also on sheet 16
DP5_M2C_N: C13.1 ; also on sheet 16
DP5_M2C_P: C14.1 ; also on sheet 16
DP6_C2M_N: C11.1 ; also on sheet 16
DP6_C2M_P: C12.1 ; also on sheet 16
DP6_M2C_N: C15.1 ; also on sheet 16
DP6_M2C_P: C16.1 ; also on sheet 16
DP7_C2M_N: C23.1 ; also on sheet 16
DP7_C2M_P: C21.1 ; also on sheet 16
DP7_M2C_N: C24.1 ; also on sheet 16
DP7_M2C_P: C22.1 ; also on sheet 16
FBBANDSEL1: J9.50 U1.H9(FBBANDSEL1)
FBBANDSEL2: J9.53 U1.N9(FBBANDSEL2)
FMC_FBBANDSEL1: J9.51
FMC_FBBANDSEL2: J9.54
FMC_FSPICLKA: R40.2 ; also on sheet 16
FMC_FSPICLKB: R42.2 ; also on sheet 16
FMC_FSPICLKC: R44.2 ; also on sheet 16
FMC_FSPICLKD: R46.2 ; also on sheet 16
FMC_FSPIDA: R41.2 ; also on sheet 16
FMC_FSPIDB: R43.2 ; also on sheet 16
FMC_FSPIDC: R45.2 ; also on sheet 16
FMC_FSPIDD: R47.2 ; also on sheet 16
FMC_RXADSA1PD: J7.9 ; also on sheet 16
FMC_RXADSA2PD: J7.12 ; also on sheet 16
FMC_RXADSAFAST: J9.3 ; also on sheet 16
FMC_RXAPD2H: J7.33 ; also on sheet 16
FMC_RXAPD2L: J7.36 ; also on sheet 16
FMC_RXBDSA1PD: J7.15 ; also on sheet 16
FMC_RXBDSA2PD: J7.18 ; also on sheet 16
FMC_RXBDSAFAST: J9.6 ; also on sheet 16
FMC_RXBPD2H: J7.39 ; also on sheet 16
FMC_RXBPD2L: J7.42 ; also on sheet 16
FMC_RXCDSA1PD: J7.21
FMC_RXCDSA2PD: J7.24
FMC_RXCDSAFAST: J9.9
FMC_RXDDSA1PD: J7.27
FMC_RXDDSA2PD: J7.30
FMC_RXDDSAFAST: J9.12
FMC_RXDSASW: J9.48 ; also on sheet 16
FMC_RXFBNCO0: J9.15
FMC_RXFBNCO1: J9.18
FMC_RXFBNCO2: J9.21
FMC_RXFBNCO3: J9.24
FMC_RXFBSW1: J9.39
FMC_RXFBSW2: J9.42
FMC_RXTDD1: J9.33
FMC_RXTDD2: J9.36
FMC_SPIACLK: J13.6 ; also on sheet 16
FMC_SPIASDIO: J13.12 ; also on sheet 16
FMC_SPIASDO: J13.9 ; also on sheet 16
FMC_SPIASEN: J13.3 ; also on sheet 16
FMC_SPIBCLK: J13.18 ; also on sheet 16
FMC_SPIBSDIO: J13.24 ; also on sheet 16
FMC_SPIBSDO: J13.21 ; also on sheet 16
FMC_SPIBSEN: J13.15 ; also on sheet 16
FMC_TCK: J10.3 ; also on sheet 16
FMC_TDI: J10.6 ; also on sheet 16
FMC_TDO: J10.9 ; also on sheet 16
FMC_TMS: J10.12 ; also on sheet 16
FMC_TRSTB: J10.15 ; also on sheet 16
FMC_TXDSASW: J9.45 ; also on sheet 16
FMC_TXTDD1: J9.27 ; also on sheet 16
FMC_TXTDD2: J9.30 ; also on sheet 16
FSPICLKA: R33.2 R40.1 U1.C11(FSPICLKA)
FSPICLKB: R35.2 R42.1 U1.C14(FSPICLKB)
FSPICLKC: R36.2 R44.1 U1.V11(FSPICLKC)
FSPICLKD: R39.2 R46.1 U1.V14(FSPICLKD)
FSPIDA: R32.2 R41.1 U1.C10(FSPIDA)
FSPIDB: R34.2 R43.1 U1.C13(FSPIDB)
FSPIDC: R37.2 R45.1 U1.V10(FSPIDC)
FSPIDD: R38.2 R47.1 U1.V13(FSPIDD)
FTDI_DSASW: C45.2 J9.43 J9.46 JP7.1 R24.1
FTDI_FBBANDSEL: C46.2 J9.49 J9.52 JP8.1 R25.1
FTDI_FSPICLKA: J12.2 ; also on sheet 21
FTDI_FSPICLKB: J12.6 ; also on sheet 21
FTDI_FSPICLKC: J12.10 ; also on sheet 21
FTDI_FSPICLKD: J12.14 ; also on sheet 21
FTDI_FSPIDA: J12.4 ; also on sheet 21
FTDI_FSPIDB: J12.8 ; also on sheet 21
FTDI_FSPIDC: J12.12 ; also on sheet 21
FTDI_FSPIDD: J12.16 ; also on sheet 21
FTDI_RXDSAFAST: C42.2 J9.1 J9.4 J9.7 J9.10 JP2.1 R27.1
FTDI_RXFBNCO: C47.2 J9.13 J9.16 J9.19 J9.22 JP3.1 R28.1
FTDI_RXFBSW: C44.2 J9.37 J9.40 JP6.1 R23.1
FTDI_RXTDD_MODE: C43.2 J9.31 J9.34 JP5.1 R22.1
FTDI_SPIACLK: J13.4 ; also on sheet 21
FTDI_SPIASDIO: J13.10 ; also on sheet 21
FTDI_SPIASDO: J13.7 ; also on sheet 21
FTDI_SPIASEN: J13.1 ; also on sheet 21
FTDI_SPIBCLK: J13.16 ; also on sheet 21
FTDI_SPIBSDIO: J13.22 ; also on sheet 21
FTDI_SPIBSDO: J13.19 ; also on sheet 21
FTDI_SPIBSEN: J13.13 ; also on sheet 21
FTDI_TCK: J10.1 ; also on sheet 21
FTDI_TDI: J10.4 ; also on sheet 21
FTDI_TDO: J10.7 ; also on sheet 21
FTDI_TMS: J10.10 ; also on sheet 21
FTDI_TRSTB: J10.13 ; also on sheet 21
FTDI_TXTDD_MODE: C48.2 J9.25 J9.28 JP4.1 R29.1
PG_RX1P85V: Q25.2(G1) R327.2 U25.4(PG)
PG_TX1P8V: R267.2 ; also on sheet 20
PLL_CLKLD: J8.3 Q2.1(B)
PLL_REFLD: J8.1 Q1.1(B)
PLLCLKLD: J8.4 U1.T16(PLLCLKLD)
PLLREFLD: J8.2 U1.E16(PLLREFLD)
RX1N: C9.2 U1.A2(SRX1M)
RX1P: C10.2 U1.A3(SRX1P)
RX2N: C12.2 U1.C1(SRX2M)
RX2P: C11.2 U1.B1(SRX2P)
RX3N: C17.2 U1.F1(SRX3M)
RX3P: C19.2 U1.E1(SRX3P)
RX4N: C21.2 U1.J1(SRX4M)
RX4P: C23.2 U1.H1(SRX4P)
RX5N: C26.2 U1.M1(SRX5M)
RX5P: C25.2 U1.N1(SRX5P)
RX6N: C31.2 U1.R1(SRX6M)
RX6P: C29.2 U1.T1(SRX6P)
RX7N: C33.2 U1.V1(SRX7M)
RX7P: C34.2 U1.W1(SRX7P)
RX8N: C37.2 U1.Y2(SRX8M)
RX8P: C39.2 U1.Y3(SRX8P)
RX_1.2V: C81.1 C82.1 C83.1 C84.1 C85.1 C86.1 C87.1 C88.1 C89.1 C90.1 U1.F5(RX1P2V) U1.F6(RX1P2V) U1.F7(RX1P2V) U1.F8(RX1P2V) U1.F9(RX1P2V) U1.F10(RX1P2V) U1.G6(RX1P2V) U1.G7(RX1P2V) U1.G8(RX1P2V) U1.P6(RX1P2V) U1.P7(RX1P2V) U1.P8(RX1P2V) U1.R5(RX1P2V) U1.R6(RX1P2V) U1.R7(RX1P2V) U1.R8(RX1P2V) U1.R9(RX1P2V) U1.R10(RX1P2V) ; also on sheet 20
RX_1.8V: C66.1 C67.1 C68.1 C69.1 C70.1 C71.1 C72.1 C73.1 C74.1 C75.1 C394.1 C395.1 FB33.3 PP22.1 U1.C5(RX1P8V) U1.C6(RX1P8V) U1.D5(RX1P8V) U1.D6(RX1P8V) U1.D9(RX1P8V) U1.D10(RX1P8V) U1.E5(RX1P8V) U1.E6(RX1P8V) U1.E9(RX1P8V) U1.E10(RX1P8V) U1.T5(RX1P8V) U1.T6(RX1P8V) U1.T9(RX1P8V) U1.T10(RX1P8V) U1.U5(RX1P8V) U1.U6(RX1P8V) U1.U9(RX1P8V) U1.U10(RX1P8V) U1.V5(RX1P8V) U1.V6(RX1P8V)
RXA_DSA1PD: J7.7 Q5.1(B)
RXA_DSA2PD: J7.10 Q6.1(B)
RXA_PD2H: J7.31 Q13.1(B)
RXA_PD2L: J7.34 Q14.1(B)
RXADSA1PD: J7.8 R302.1
RXADSA2PD: J7.11 R303.1
RXADSAFAST: J9.2 U1.E14(RXADSAFAST)
RXAPD2H: J7.32 R315.1
RXAPD2L: J7.35 R316.1
RXB_DSA1PD: J7.13 Q7.1(B)
RXB_DSA2PD: J7.16 Q8.1(B)
RXB_PD2H: J7.37 Q15.1(B)
RXB_PD2L: J7.40 Q16.1(B)
RXBDSA1PD: J7.14 R309.1
RXBDSA2PD: J7.17 R310.1
RXBDSAFAST: J9.5 U1.F11(RXBDSAFAST)
RXBPD2H: J7.38 R317.1
RXBPD2L: J7.41 R318.1
RXC_DSA1PD: J7.19 Q9.1(B)
RXC_DSA2PD: J7.22 Q10.1(B)
RXC_PD2H: J7.43 Q17.1(B)
RXC_PD2L: J7.46 Q18.1(B)
RXCDSA1PD: J7.20 R311.1
RXCDSA2PD: J7.23 R312.1
RXCDSAFAST: J9.8 U1.T14(RXCDSAFAST)
RXCPD2H: J7.44 R319.1
RXCPD2L: J7.47 R320.1
RXD_DSA1PD: J7.25 Q11.1(B)
RXD_DSA2PD: J7.28 Q12.1(B)
RXD_PD2H: J7.49 Q19.1(B)
RXD_PD2L: J7.52 Q20.1(B)
RXDDSA1PD: J7.26 R313.1
RXDDSA2PD: J7.29 R314.1
RXDDSAFAST: J9.11 U1.R11(RXDDSAFAST)
RXDPD2H: J7.50 R304.1
RXDPD2L: J7.53 R305.1
RXDSASW: J9.47 U1.D13(RXDSASW)
RXFBNCO0: J9.14 U1.C12(RXFBNCO0)
RXFBNCO1: J9.17 U1.G9(RXFBNCO1)
RXFBNCO2: J9.20 U1.V12(RXFBNCO2)
RXFBNCO3: J9.23 U1.P9(RXFBNCO3)
RXFBSW1: J9.38 U1.E11(RXFBSW1)
RXFBSW2: J9.41 U1.T11(RXFBSW2)
RXTDD1: J9.32 U1.D7(RXTDD1)
RXTDD2: J9.35 U1.U7(RXTDD2)
SLEEPMODE: J9.62 U1.P5(SLEEPMODE)
SPIACLK: J13.5 U1.D14(SPIACLK)
SPIASDIO: J13.11 U1.E15(SPIASDIO)
SPIASDO: J13.8 U1.C15(SPIASDO)
SPIASEN: J13.2 U1.D15(SPIASEN)
SPIBCLK: J13.17 U1.U14(SPIBCLK)
SPIBSDIO: J13.23 U1.T15(SPIBSDIO)
SPIBSDO: J13.20 U1.V15(SPIBSDO)
SPIBSEN: J13.14 U1.U15(SPIBSEN)
syncb0cmos: U1.E13(syncb0cmos) ; also on sheet 16
syncb1cmos: U1.C8(syncb1cmos) ; also on sheet 16
syncb2cmos: U1.T13(syncb2cmos) ; also on sheet 16
syncb3cmos: U1.V8(syncb3cmos) ; also on sheet 16
SYSREF-N: R13.2 R14.1 R296.1 U1.L14(SYSREFM)
SYSREF-P: R11.1 R12.2 R296.2 U1.K14(SYSREFP)
SYSREFN: R13.1 ; also on sheet 14
SYSREFP: R12.1 ; also on sheet 14
TCLK: J10.2 U1.K5(TCLK)
TDI: J10.5 U1.L5(TDI)
TDO: J10.8 U1.H5(TDO)
TMS: J10.11 U1.N5(TMS)
TRST: J10.14 R30.1 U1.M5(TRST)
TX1ENB: J9.56 U1.D16(TXENB1)
TX1N: C14.2 U1.C3(STX1M)
TX1P: C13.2 U1.C4(STX1P)
TX2ENB: J9.59 U1.U16(TXENB2)
TX2N: C16.2 U1.E3(STX2M)
TX2P: C15.2 U1.E4(STX2P)
TX3N: C18.2 U1.G3(STX3M)
TX3P: C20.2 U1.G4(STX3P)
TX4N: C22.2 U1.J3(STX4M)
TX4P: C24.2 U1.J4(STX4P)
TX5N: C27.2 U1.M3(STX5M)
TX5P: C28.2 U1.M4(STX5P)
TX6N: C32.2 U1.P3(STX6M)
TX6P: C30.2 U1.P4(STX6P)
TX7N: C35.2 U1.T3(STX7M)
TX7P: C36.2 U1.T4(STX7P)
TX8N: C38.2 U1.V3(STX8M)
TX8P: C40.2 U1.V4(STX8P)
TXAM: U1.C20(TXAM) ; also on sheet 12
TXAP: U1.B20(TXAP) ; also on sheet 12
TXBM: U1.F20(TXBM) ; also on sheet 12
TXBP: U1.G20(TXBP) ; also on sheet 12
TXCM: U1.W20(TXCP) ; also on sheet 13
TXCP: U1.V20(TXCM) ; also on sheet 13
TXDM: U1.P20(TXDP) ; also on sheet 13
TXDP: U1.R20(TXDM) ; also on sheet 13
TXDSASW: J9.44 U1.U13(TXDSASW)
TXTDD1: J9.26 U1.C16(TXTDD1)
TXTDD2: J9.29 U1.V16(TXTDD2)
N18858492: R3.1 R322.2 T3.4(SEC)
N18858499: C4.2 R4.1 R7.1
N18858501: R10.1 R323.2 T3.6(SEC_DOT)
N18893180: C133.1 R351.2 T5.6(PRI_DOT)
N19075291: R31.2 U1.V18(RBIAS)
N19075362: C49.1 U1.U18(EXTO)
N19075631: J11.1 U1.M15(ATESTTX)
N19075640: J11.3 U1.H8(VSENSE)
N19075649: J11.5 U1.N8(IFORCE)
N19075658: J11.7 U1.K2(AMUX1)
N19075667: J11.9 U1.L2(AMUX2)
N19098122: C127.2 C129.2 L3.2
N19098132: C130.2 C133.2 L3.1
N19098142: C130.1 L5.1 R58.2
N19098149: C129.1 L5.2 R48.2
N19098687: C131.2 R48.1
N19098701: C136.2 R58.1
N19191731: R4.2 T2.2(PRI_DOT)
N19192217: C7.1 R8.2 R9.1
N19192242: C7.2 T3.2(PRI_DOT)
N19192342: R8.1 T2.4(SEC)
N19192872: C1.1 R1.2 R2.1
N19192989: R1.1 T2.6(SEC_DOT)
N19193468: C41.1 R17.2 SW1.2 U1.C18(RESETZ)
N19245147: C132.1 L6.2 R52.2 R54.2
N19261159: J2.1(CENTER) R3.2
N19261175: J4.1(CENTER) R10.2
N19261803: J5.1(CENTER) R11.2
N19261938: J6.1(CENTER) R14.2
N19265268: R302.2 U1.E8(RXADSA1PD)
N19265271: R303.2 U1.C9(RXADSA2PD)
N19265297: R309.2 U1.E12(RXBDSA1PD)
N19265300: R310.2 U1.D12(RXBDSA2PD)
N19265317: R311.2 U1.T8(RXCDSA1PD)
N19265320: R312.2 U1.V9(RXCDSA2PD)
N19265379: R313.2 U1.T12(RXDDSA1PD)
N19265382: R314.2 U1.U12(RXDDSA2PD)
N19265545: R315.2 U1.D8(RXAPD2H)
N19265548: R316.2 U1.D11(RXAPD2L)
N19265574: R317.2 U1.C7(RXBPD2H)
N19265577: R318.2 U1.E7(RXBPD2L)
N19265594: R319.2 U1.U8(RXCPD2H)
N19265597: R320.2 U1.U11(RXCPD2L)
N19265616: R304.2 U1.V7(RXDPD2H)
N19265619: R305.2 U1.T7(RXDPD2L)
N19353777: C127.1 R350.2 T5.4(PRI)
N19392140: C6.2 T1.6(secondary_dot)
N19392142: C6.1 R5.1 U1.L15(CLKOUTM)
N19392187: C2.1 R5.2 U1.K15(CLKOUTP)
N19392195: C3.1 T1.3(primary_dot)
N19392206: C3.2 J3.1(CENTER) R6.2
N19393571: R21.1 U1.G5(DACOUT)
N19439857: J12.1 R33.1
N19439882: J12.3 R32.1
N19439919: J12.5 R35.1
N19439930: J12.7 R34.1
N19439963: J12.9 R36.1
N19439974: J12.11 R37.1
N19440007: J12.13 R39.1
N19440018: J12.15 R38.1
N19452593: Q1.3(C) R18.2
N19452616: D1.2(CATHODE) R18.1
N19452717: Q2.3(C) R19.2
N19452732: D2.2(CATHODE) R19.1
N19467594: R20.1 U1.J5(SCANEN)
N19500229: Q3.3(C) Q4.3(C) Q5.3(C) Q6.3(C) Q7.3(C) Q8.3(C) Q9.3(C) Q10.3(C) Q11.3(C) Q12.3(C) Q13.3(C) Q14.3(C) Q15.3(C) Q16.3(C) Q17.3(C) Q18.3(C) Q19.3(C) Q20.3(C) R26.2
N19509945: D3.2(CATHODE) R26.1
N19816997: C2.2 T1.4(secondary)
N20069404: Q25.3(D2) Q25.D2(DRAIN2) R307.1 U13.3(EN)
N20069410: L45.1 U13.7(SW)
N20069434: R228.1 R233.2 U13.5(FB)
N20069572: FB18.1 RS1.1 U15.3(VIN+)
N20069690: Q25.5(G2) Q25.6(D1) Q25.D1(DRAIN1) R306.1
N20069712: PP3.1 R229.1 R232.1
N20069759: R229.2 U15.1(OUT)
N20086063: R270.2 U25.6(100mV)
N20086075: C397.1 C398.1 C454.1 RS6.2 U25.1(OUT1) U25.19(OUT2) U25.20(OUT3) U26.3(VIN+)
N20086085: C401.1 U25.12(BIAS)
N20086089: R271.2 U25.7(200mV)
N20086091: C399.1 U25.3(FB)
N20086095: R272.2 U25.10(800mV)
N20086131: PP23.1 R268.1 R269.1
N20086161: R268.2 U26.1(OUT)
N20086199: C400.1 U25.13(NR/SS)
N20086237: R267.1 U25.14(EN)
N20133985: R351.1 T4.5(SEC) T5.1(SEC_DOT)
N20133989: R350.1 T4.4(SEC_DOT) T5.3(SEC)
N20135778: C135.2 T5.2(NC)
N20136307: C141.1 R354.2 T9.4(PRI)
N20136325: C141.2 C142.2 L9.2
N20136327: C140.2 C143.2 L9.1
N20136329: C143.1 L10.1 R77.2
N20136331: C142.1 L10.2 R73.2
N20136361: R355.1 T8.5(SEC) T9.1(SEC_DOT)
N20136363: R354.1 T8.4(SEC_DOT) T9.3(SEC)
N20136391: C144.2 R73.1
N20136393: C145.2 R77.1
N20136405: C137.1 L4.2 R74.2 R76.2
N20136526: C140.1 R355.2 T9.6(PRI_DOT)
N20136572: C139.2 T9.2(NC)
N20221008: C469.1 R352.2 T7.4(PRI)
N20221026: C469.2 C472.2 L52.2
N20221028: C470.2 C473.2 L52.1
N20221030: C473.1 L53.1 R334.2
N20221032: C472.1 L53.2 R333.2
N20221062: R353.1 T6.5(SEC) T7.1(SEC_DOT)
N20221064: R352.1 T6.4(SEC_DOT) T7.3(SEC)
N20221092: C474.2 R333.1
N20221094: C475.2 R334.1
N20221106: C471.1 L50.2 R331.2 R332.2
N20221227: C470.1 R353.2 T7.6(PRI_DOT)
N20221265: C476.2 T7.2(NC)
N20221700: R357.1 T10.5(SEC) T11.1(SEC_DOT)
N20221704: C477.1 R356.2 T11.4(PRI)
N20221714: C477.2 C480.2 L56.2
N20221716: C478.2 C481.2 L56.1
N20221718: C481.1 L57.1 R339.2
N20221720: C480.1 L57.2 R338.2
N20221748: R356.1 T10.4(SEC_DOT) T11.3(SEC)
N20221780: C482.2 R338.1
N20221782: C483.2 R339.1
N20221794: C479.1 L54.2 R336.2 R337.2
N20221915: C478.1 R357.2 T11.6(PRI_DOT)
N20221947: C484.2 T11.2(NC)

Not connected (* = marked no-connect by the designer): J7 3 6 45* 48* 51* 54*; T1 5(NC)*; T4 6(NC1)*; T6 6(NC1)*; T8 6(NC1)*; T10 6(NC1)*; U13 8(PG)*; U25 5(50mV) 9(400mV)* 11(1.6V)*

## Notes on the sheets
sheet 2
- 6
- place on the same layer
  of device fo rminumum
  inductance
- 7
sheet 3
- AFE74XX on-chip PLL mode
        LMK04828 provides
       up to 800MHz of clock
- DACCLK
- AFE7422
- USB PORT
- AFE7444
- PAGE 15
- SYSREF
- PAGES 2-11
- PAGE 12,13
- Direct clocking mode
         EXT SMA
  (on-chip PLL bypassed)
- PAGE 12,13
- JESD204B
- INTERFACE
- PAGE 13
- POWER SUPPLIES
- PAGE 16-20
- Drawn:
- L NGUYEN     05/2018
- Engineer:
- K HSIA
sheet 4
- NOTE:
  1.8Vpp into 50ohm
- Shared pad
- Shared pad
- Shared pad
- Shared pad
- NOTE:
  CLKP/CLKN & SYSREFP/SYSREFN accepts 0.45Vcm
  with 0.9Vpp of AC swing single-ended.
  This is 1.8Vpp differential swing.
sheet 5
- CARRIER = TSW14J56/TSW14J57
  MEZZANINE = EVM
  M2C = Mezzanine to Carrier
  C2M = Carrier to Mezzanine
sheet 6
- SHORT 1-2,4-5,7-8,10-11,13-14,16-17,19-20,
  22-23,25-26,28-29,31-32,34-35, 37-38,
  40-41,43-44,46-47,49-50,52-53
- SHORT 1-2,4-5,7-8,10-11,13-14,16-17,19-20,
  22-23,25-26,28-29,31-32,34-35, 37-38,40-41,
  43-44,46-47,49-50,52-53,56-57,59-60,61-62
sheet 7
- MATCHED LENGTH
- MATCHED LENGTH
- Place on the same layer as DUT
- MATCHED LENGTH
sheet 10
- Shared Pad
- Shared Pad
- Shared Pad
- Shared Pad
- Shared Pad
- Shared Pad
- Shared Pad
- Shared Pad
- Shared Pad
- Shared Pad
- Shared Pad
- Shared Pad
- Shared Pad
- Shared Pad
- Shared Pad
- Shared Pad
